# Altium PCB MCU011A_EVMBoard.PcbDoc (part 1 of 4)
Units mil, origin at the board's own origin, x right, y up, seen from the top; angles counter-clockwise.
Board outline 10115 x 9285 mil, 4 copper layers (Top Layer, GND, PWR, Bottom Layer), stack 61.2 mil thick; 438 components, 207 nets, 1196 pads, 248 vias.
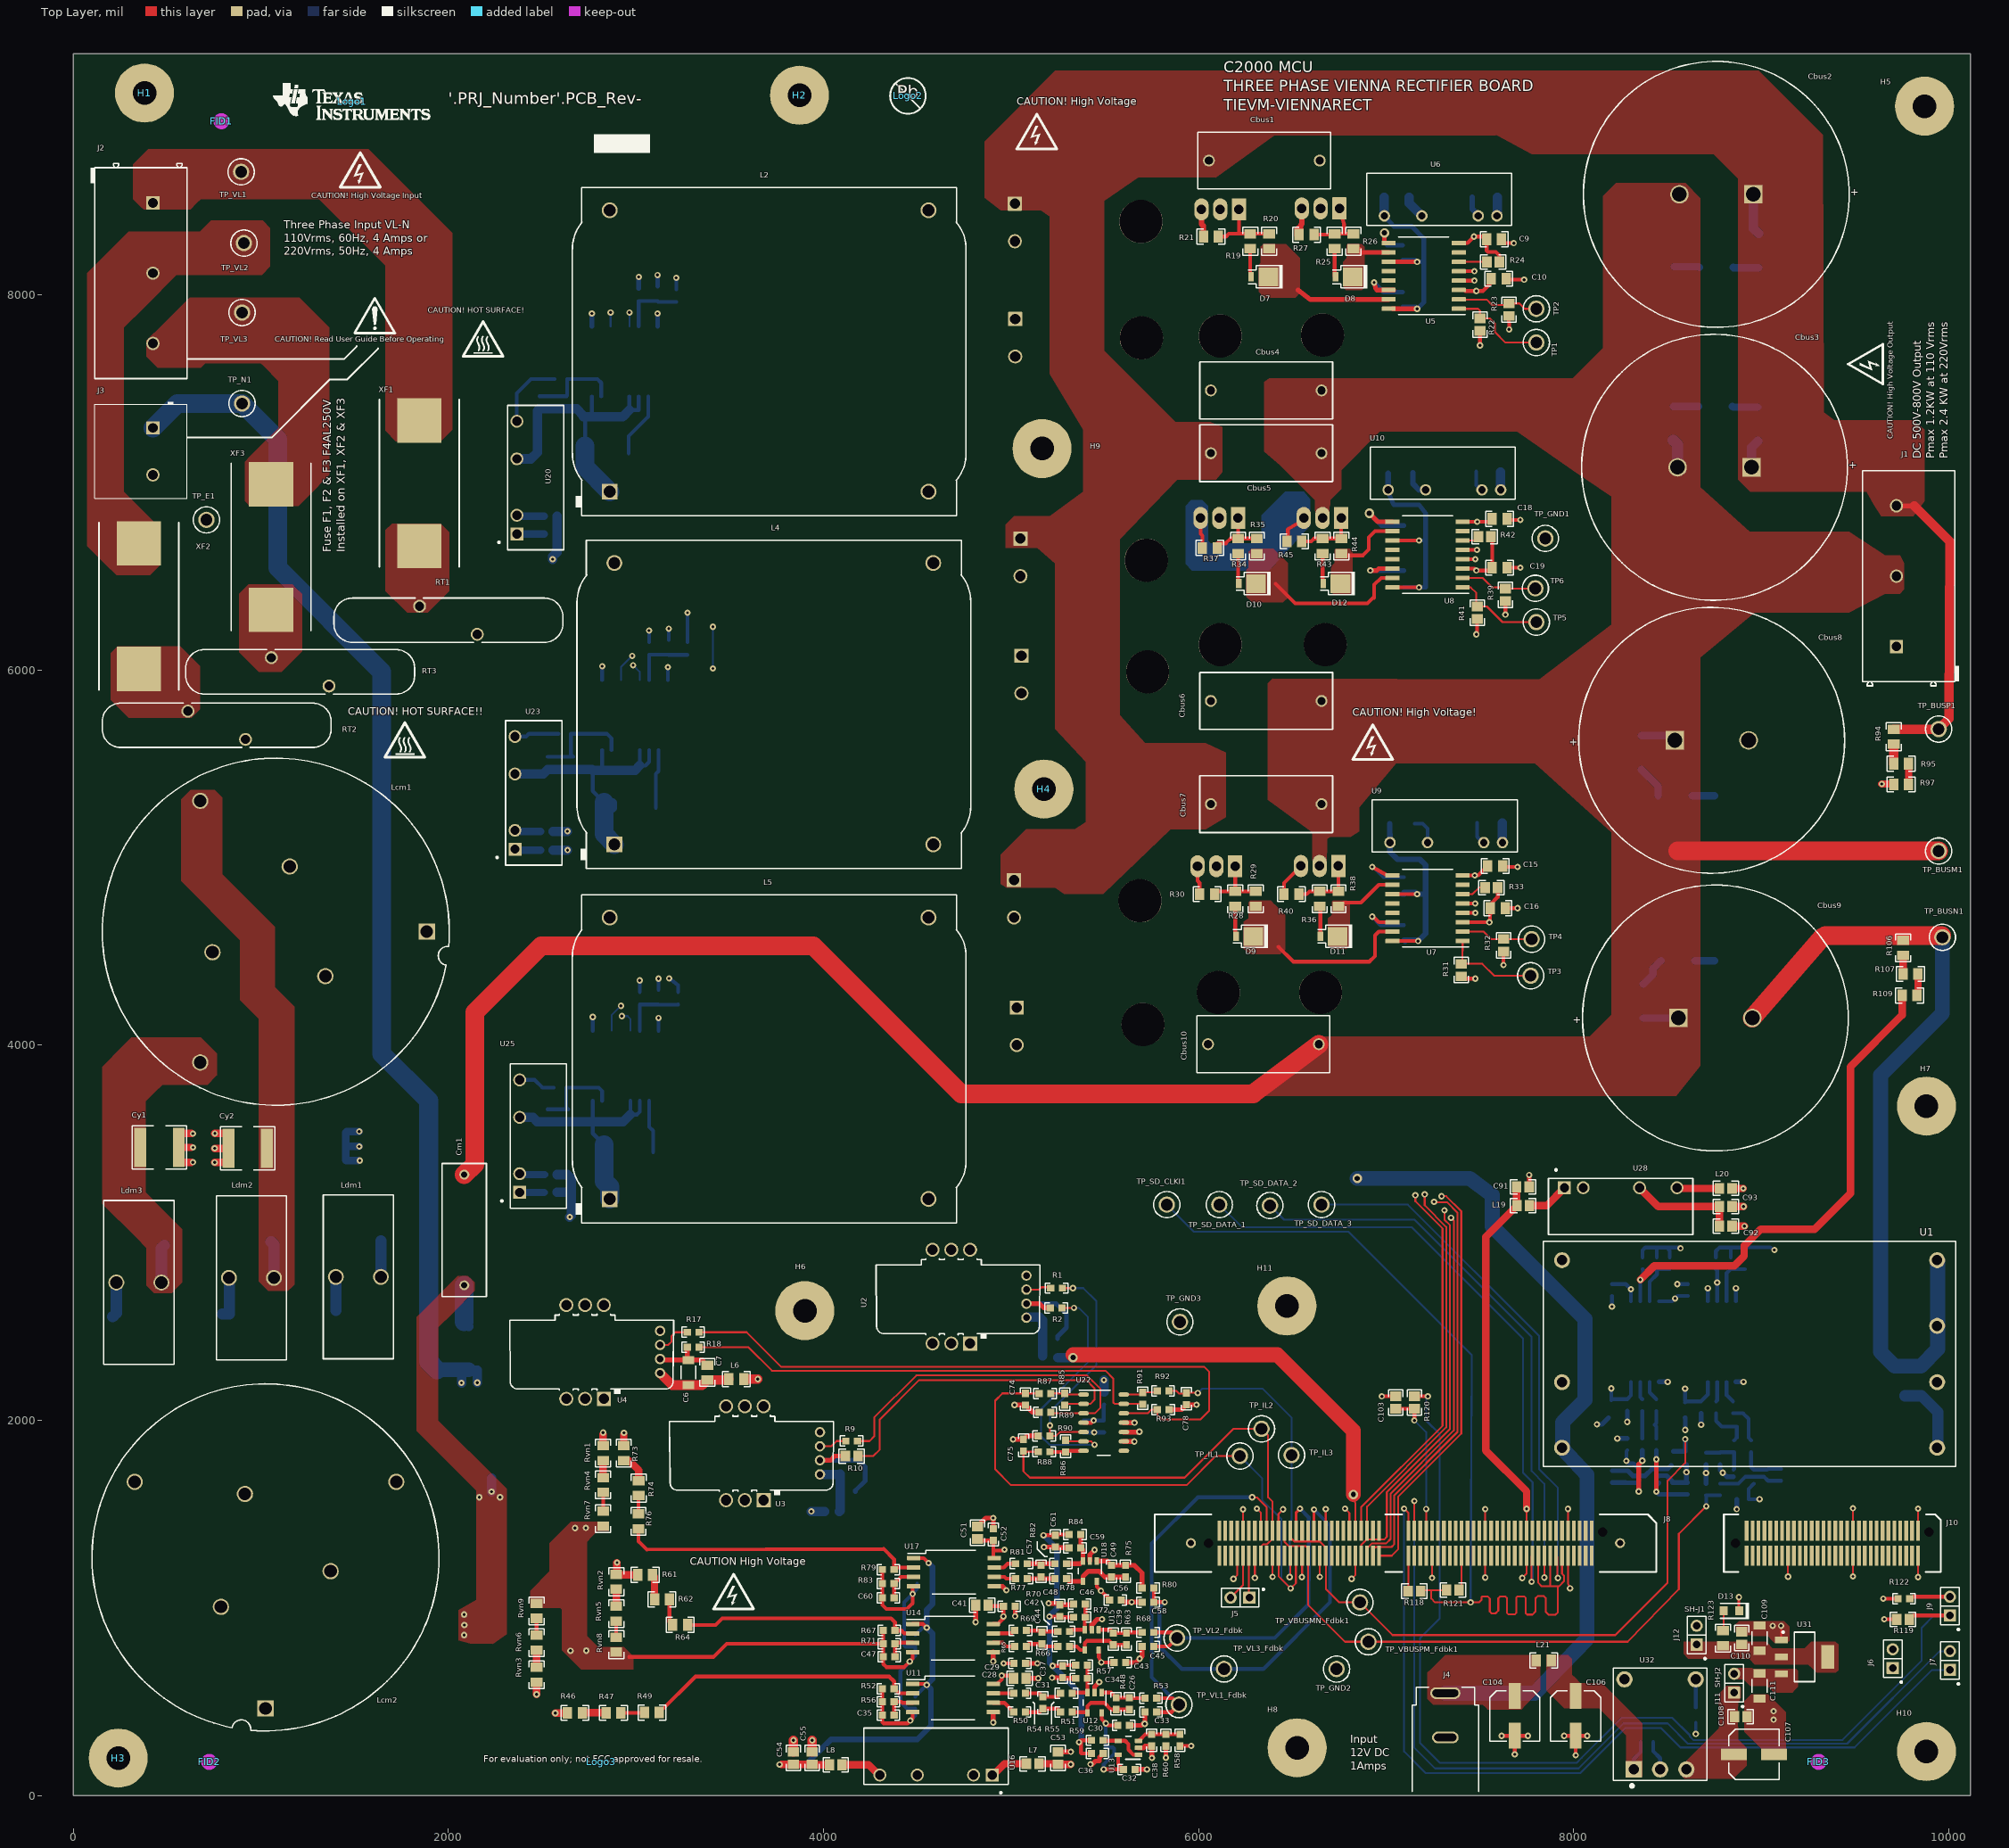
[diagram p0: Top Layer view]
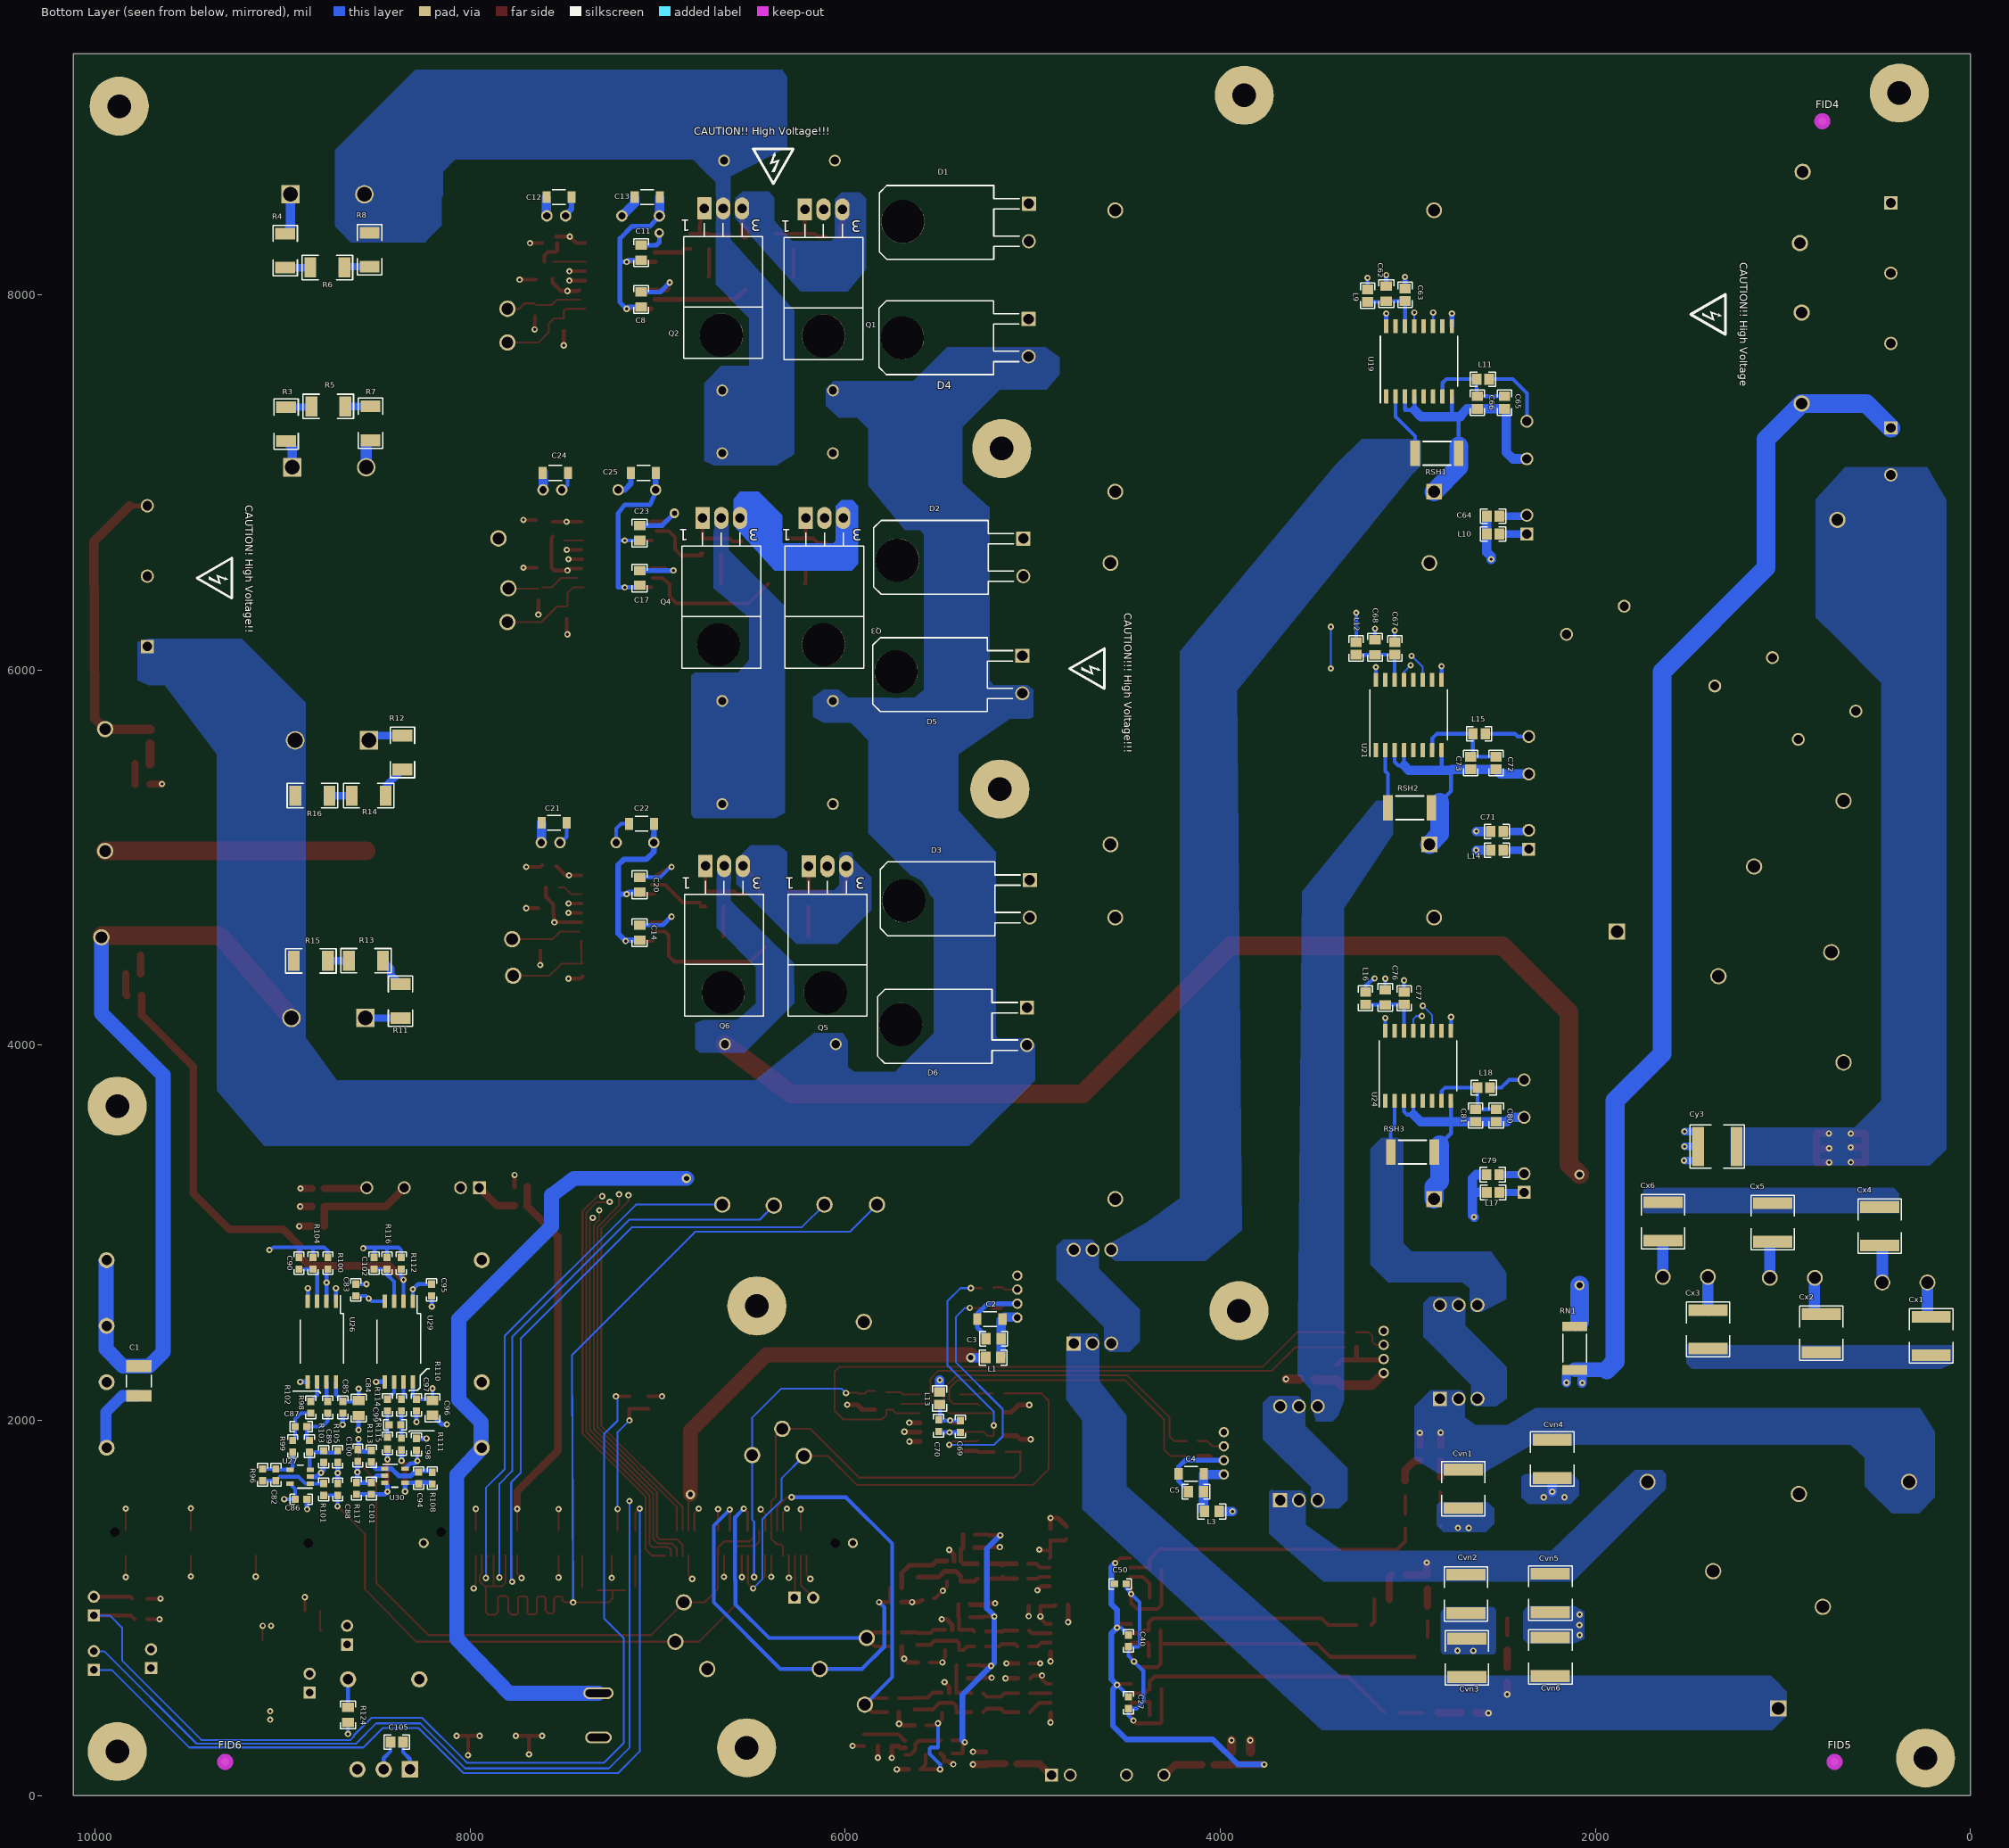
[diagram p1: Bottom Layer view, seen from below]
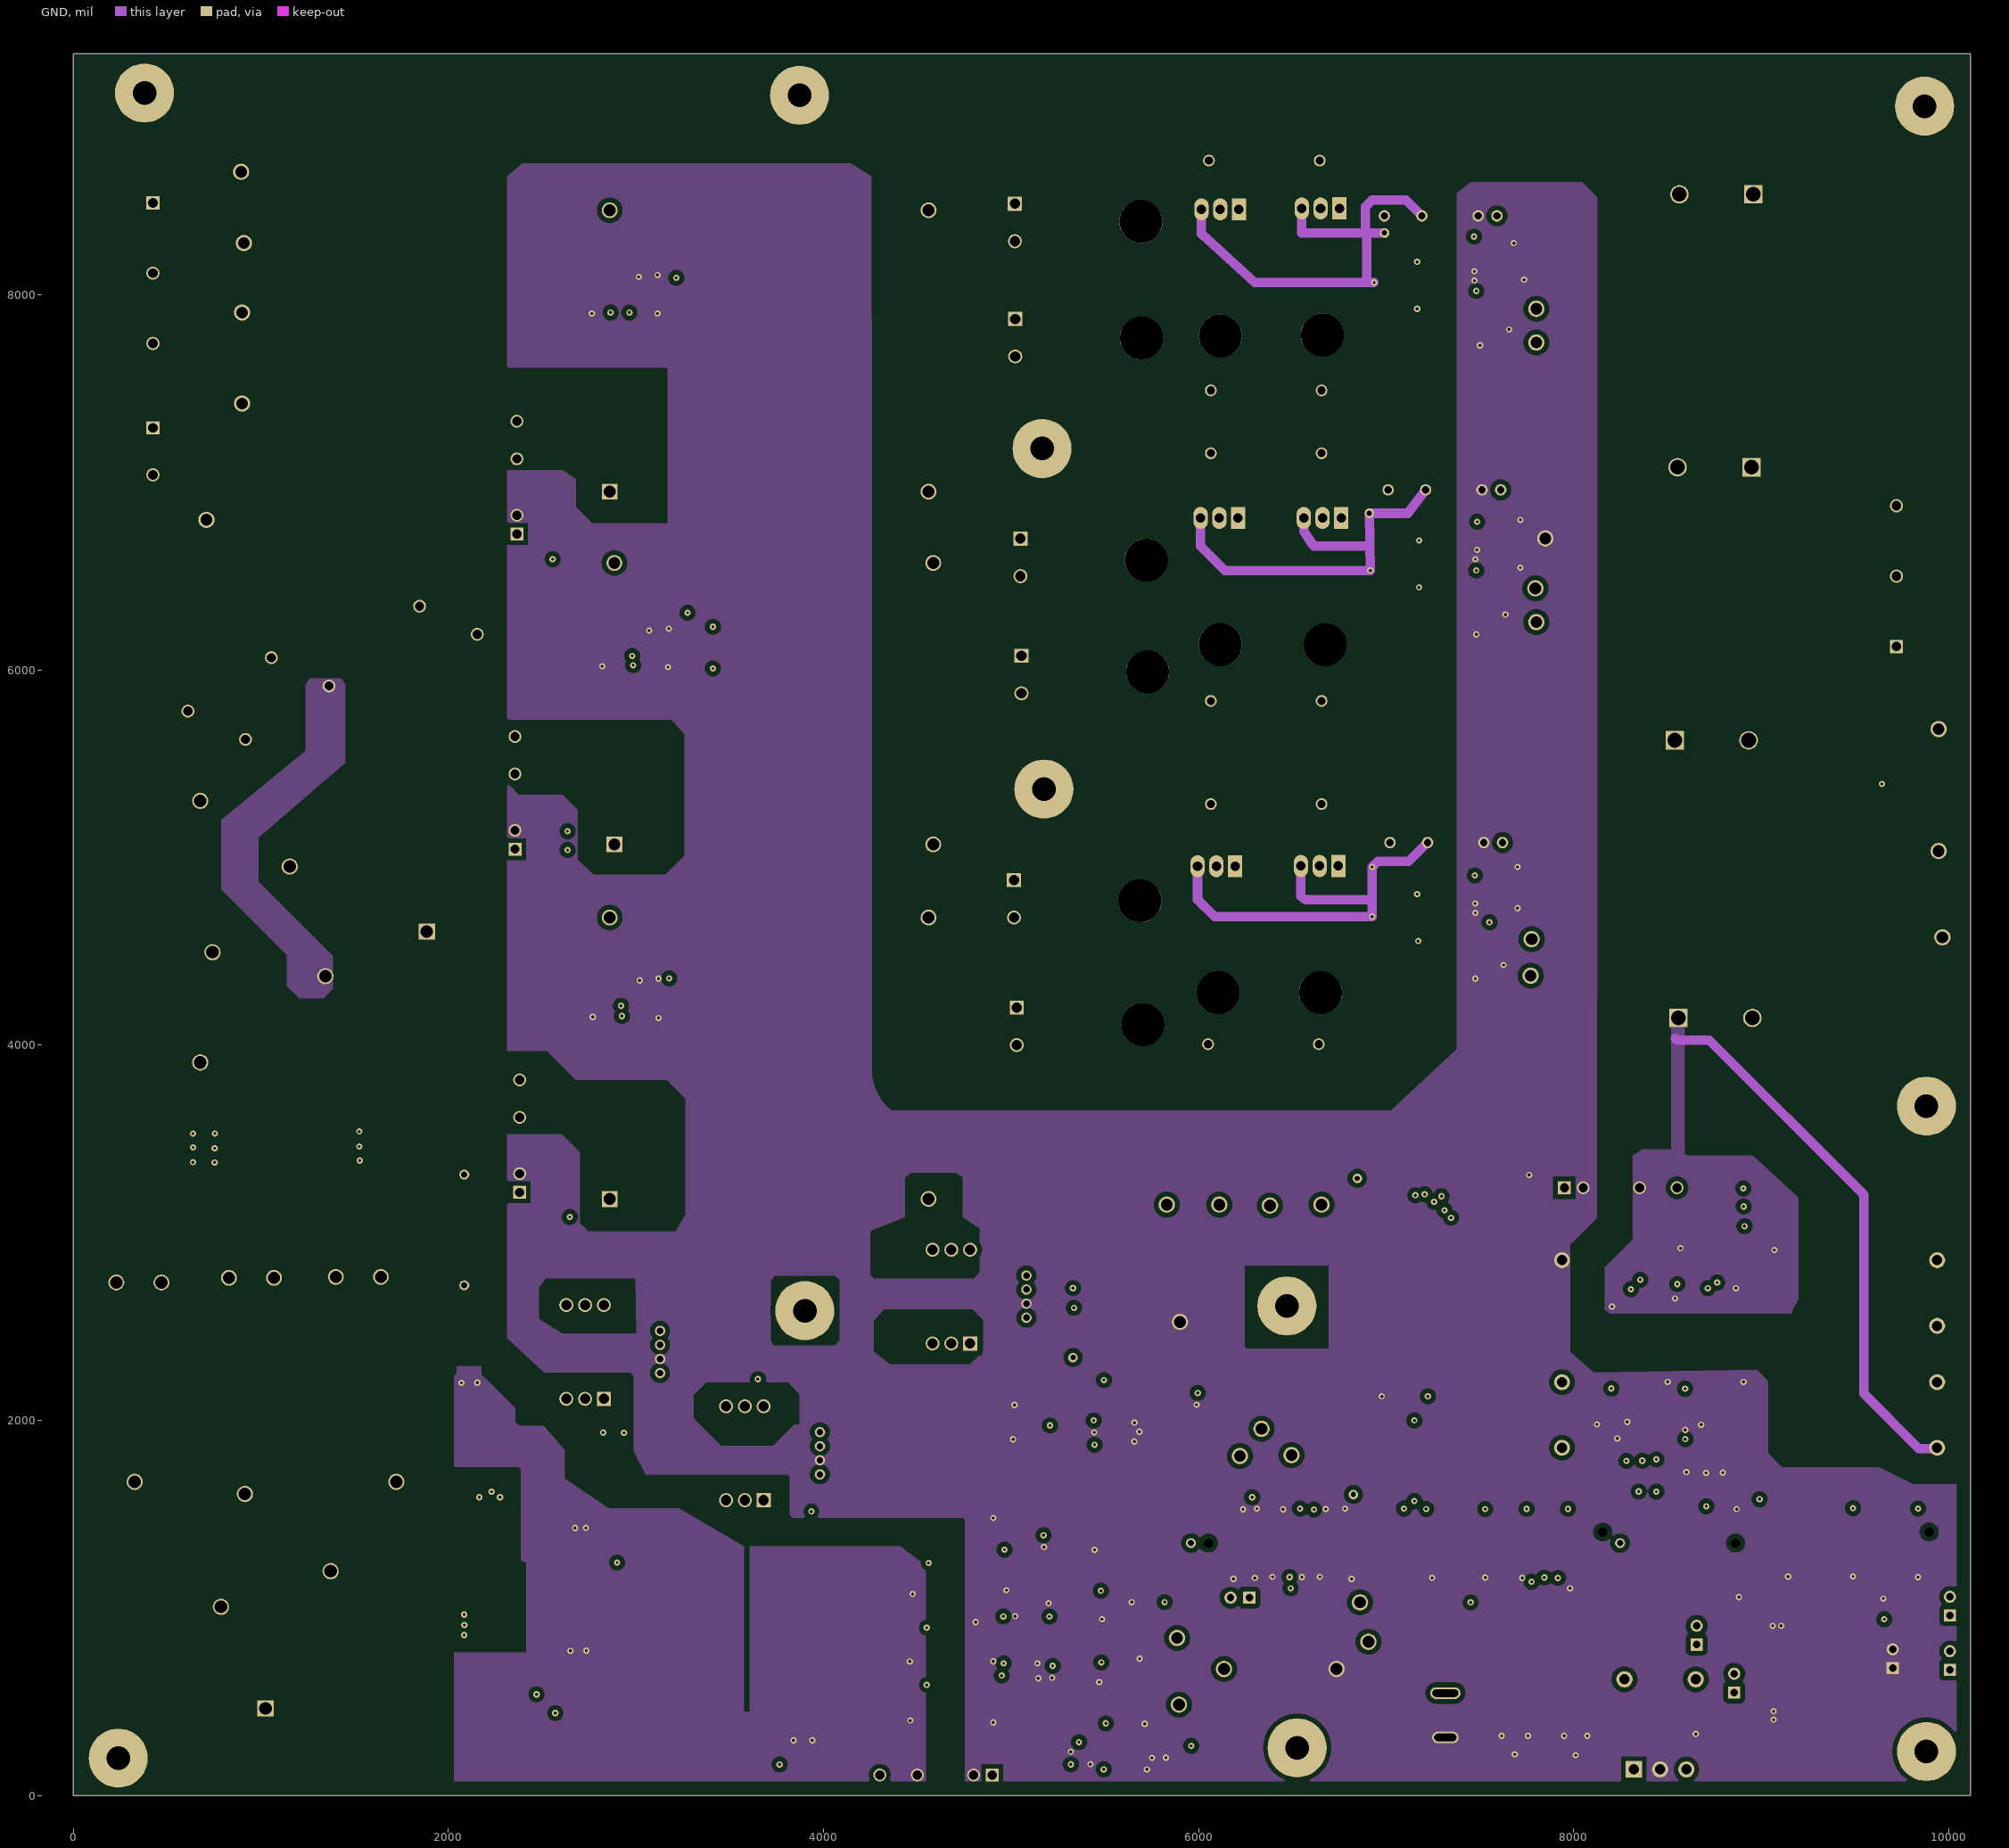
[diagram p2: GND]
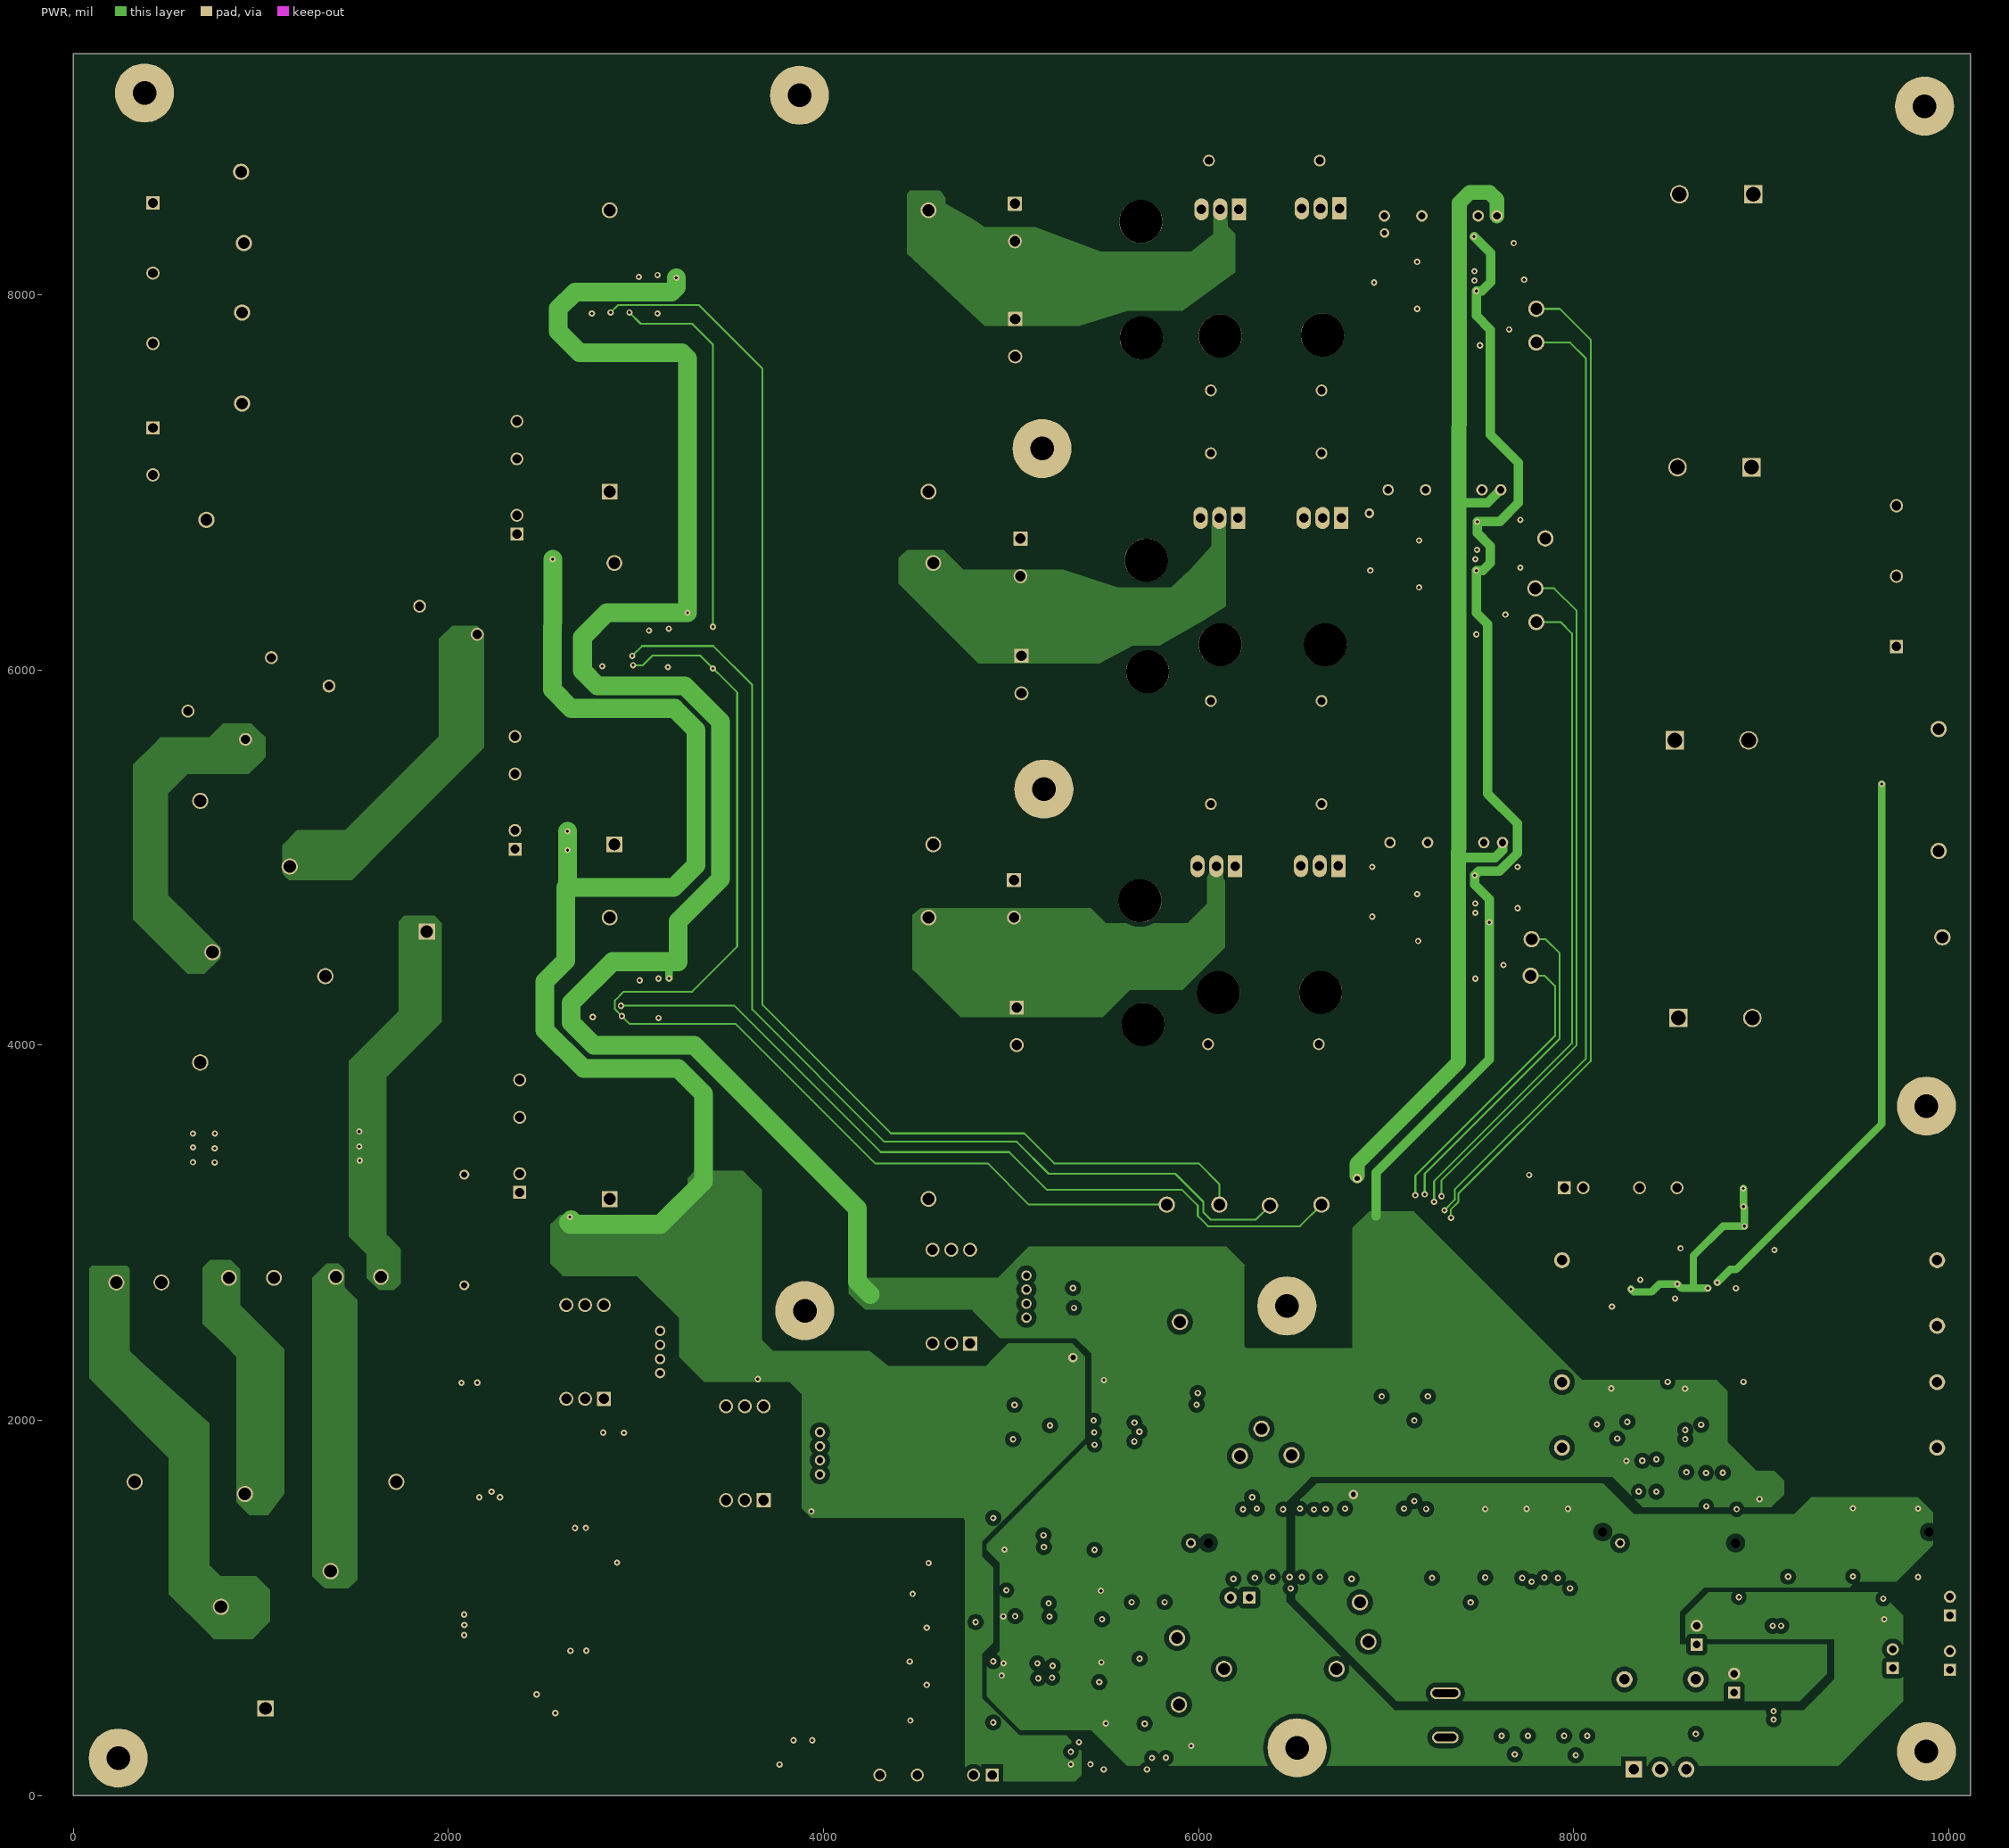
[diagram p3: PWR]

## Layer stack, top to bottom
Top Solder: solder mask 0.4, Solder Resist, Dk 3.5
Top Layer: signal copper 2.8
Dielectric1: core 15, FR-4, Dk 4.8
GND: signal copper 2.8
Dielectric 3: prepreg 20, FR-4, Dk 4.2
PWR: signal copper 2.8
Dielectric 2: core 15, FR-4, Dk 4.2
Bottom Layer: signal copper 2.8
Bottom Solder: solder mask 0.4, Solder Resist, Dk 3.5

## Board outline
0,0 10115,0 10115,9285 0,9285

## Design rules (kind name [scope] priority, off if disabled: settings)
AcuteAngle [All] p1: minimum=4.50000000000000E+0001 checktracksonly=FALSE
AssemblyTestPointUsage [All] p1: valid=2
BoardOutlineClearance BoardOutlineClearance_MountingHoles [OnCopper and InComponentClass('Mounting Holes')] p1: gap=40 ignorepadtopadclearanceinfootprint=FALSE
BoardOutlineClearance BoardOutlineClearance_Poly [OnCopper and InPoly] p2: gap=25 ignorepadtopadclearanceinfootprint=FALSE
BoardOutlineClearance [OnCopper and Not InComponentClass('Logo') and not InComponentClass('FiducialMark') and not InRegion(1000,500,4000,800)] p3: gap=75 ignorepadtopadclearanceinfootprint=FALSE
Clearance Clearance_100 [InNetClass('100')] p1: gap=100 ignorepadtopadclearanceinfootprint=FALSE except(0: Arc-Hole Track-Hole SMDPad-Hole THPad-Hole Via-Hole Fill-Hole Poly-Hole Region-Hole Text-Hole)
Clearance Clearance_Keepouts [((IsTrack Or IsArc) And Not InPoly) And IsFree and IsKeepOut vs ((IsTrack Or IsArc) And Not InPoly) And IsFree and IsKeepOut] p2: gap=0 ignorepadtopadclearanceinfootprint=FALSE
Clearance Clearance_Poly [InPolygon] p3: gap=25 ignorepadtopadclearanceinfootprint=FALSE except(0: Arc-Hole Track-Hole SMDPad-Hole THPad-Hole Via-Hole Fill-Hole Poly-Hole Region-Hole Text-Hole)
Clearance [All] p4: gap=10 ignorepadtopadclearanceinfootprint=FALSE except(0: Arc-Hole Track-Hole SMDPad-Hole THPad-Hole Via-Hole Fill-Hole Poly-Hole Region-Hole Text-Hole)
ComponentClearance ComponentClearance_MountingHoles_FiducialMarks [InComponentClass('Mounting Holes') vs InComponentClass('FiducialMark')] p1: gap=50 collisioncheckmode=3 verticalgap=10 showdistances=FALSE
ComponentClearance ComponentClearance_Shunt [InComponentClass('Header') vs InComponentClass('Shunt')] p2: gap=0 collisioncheckmode=3 verticalgap=0 showdistances=FALSE
ComponentClearance ComponentClearance_Logo [InComponentClass('Logo')] p3: gap=50 collisioncheckmode=3 verticalgap=10 showdistances=FALSE
ComponentClearance ComponentClearance_ScrewToNut [(HasFootprint('NY PMS 440 0025 PH')) vs (HasFootprint('Keystone_1902C'))] p4: gap=5 collisioncheckmode=3 verticalgap=10 showdistances=FALSE
ComponentClearance ComponentClearance_MountingHoles [InComponentClass('Mounting Holes')] p5: gap=250 collisioncheckmode=3 verticalgap=100000 showdistances=FALSE
ComponentClearance ComponentClearance_SmallPassives [HasFootprint('0201*') or HasFootprint('0402*') or HasFootprint('0508') or HasFootprint('0603*') or HasFootprint('0612') or HasFootprint('0805*') or HasFootprint('0815*') or HasFootprint('0830*') or HasFootprint('1206*') or HasFootprint('1210*') or HasFootprint('1808*') or HasFootprint('1812*') or HasFootprint('1825*') or HasFootprint('2010*') or HasFootprint('2220*') or HasFootprint('2225*') or HasFootprint('2512*') or HasFootprint('2728*') or HasFootprint('3518*') vs HasFootprint('0201*') or HasFootprint('0402*') or HasFootprint('0508') or HasFootprint('0603*') or HasFootprint('0612') or HasFootprint('0805*') or HasFootprint('0815*') or HasFootprint('0830*') or HasFootprint('1206*') or HasFootprint('1210*') or HasFootprint('1808*') or HasFootprint('1812*') or HasFootprint('1825*') or HasFootprint('2010*') or HasFootprint('2220*') or HasFootprint('2225*') or HasFootprint('2512*') or HasFootprint('2728*') or HasFootprint('3518*')] p6: gap=14.96 collisioncheckmode=3 verticalgap=10 showdistances=FALSE
ComponentClearance ComponentClearance_THtoSMT [IsThruComponent vs IsSMTComponent] p7: gap=40 collisioncheckmode=3 verticalgap=30 showdistances=FALSE
ComponentClearance ComponentClearance_THtoTH [IsThruComponent vs IsThruComponent] p8: gap=30 collisioncheckmode=3 verticalgap=30 showdistances=FALSE
ComponentClearance [All] p9: gap=30 collisioncheckmode=3 verticalgap=10 showdistances=FALSE
DiffPairsRouting [All] p1: maxlimit=100 minlimit=10 mostfreqgap=10 toplayer_minwidth=15 toplayer_maxwidth=15 toplayer_prefwidth=15 midlayer1_minwidth=15 midlayer1_maxwidth=15 midlayer1_prefwidth=15 midlayer2_minwidth=15 midlayer2_maxwidth=15 midlayer2_prefwidth=15 bottomlayer_minwidth=15 bottomlayer_maxwidth=15 bottomlayer_prefwidth=15 maxuncoupledlength=1000
FabricationTestPointUsage TestPointUsage [All] p1: valid=2 allowmultiple=FALSE
FabricationTestpoint Testpoint [All] p1: side=3 testpointundercomponent=TRUE minsize=40 maxsize=100 preferedsize=60 minholesize=0 maxholesize=40 preferedholesize=32 testpointgrid=1 allowsidetop=TRUE allowsidebottom=TRUE usegrid=TRUE gridtolerance=0.01
FanoutControl Fanout_LCC [IsLCC] p1: bgadir=Out bgaviamode=Centered fanoutstyle=Auto fanoutdirection=Alternating viagrid=1 // Fanout_LCC (Default Rule)
FanoutControl Fanout_BGA [IsBGA] p2: bgadir=Out bgaviamode=Centered fanoutstyle=Auto fanoutdirection=Alternating viagrid=1 // Fanout_BGA (Default Rule)
FanoutControl Fanout_Default [All] p4: bgadir=Out bgaviamode=Centered fanoutstyle=Auto fanoutdirection=Alternating viagrid=1 // Fanout_Default (Default Rule)
FanoutControl Fanout_Small [(CompPinCount < 5)] p5: bgadir=Out bgaviamode=Centered fanoutstyle=Auto fanoutdirection=OutThenIn viagrid=1 // Fanout_Small (Default Rule)
Height [All] p1: minheight=0 maxheight=2100 prefheight=500
HoleSize [All] p1: absolutevalues=TRUE maxlimit=251 minlimit=7.87 maxpercent=80.000 minpercent=20.000
MinimumAnnularRing MinimumAnnularRing_ThermalPadVias [IsVia and InAnyComponent] p1: minimumring=5.91
MinimumAnnularRing [All] p2: minimumring=8
MinimumSolderMaskSliver MinimumSolderMaskSliver_Logo [InComponentClass('Logo') vs InComponentClass('Logo')] p1: minsoldermaskwidth=0.7
MinimumSolderMaskSliver [All] p2: minsoldermaskwidth=3.94
PlaneConnect [All] p1: planeconnectstyle=Direct reliefexpansion=10 reliefentries=4 reliefconductorwidth=10 reliefairgap=10
PolygonConnect [All] p1: connectstyle=Direct reliefconductorwidth=10 reliefentries=4 polygonreliefangle="90 Angle" airgapwidth=10
RoutingVias ThermalPadVias [IsVia and InAnyComponent] p1: holewidth=7.87 width=19.68 viastyle="Through Hole" minholewidth=7.87 minwidth=19.68 maxholewidth=12.99 maxwidth=23.62
RoutingVias [All] p2: holewidth=16 width=34 viastyle="Through Hole" minholewidth=7.87 minwidth=26 maxholewidth=40 maxwidth=65
SilkToBoardRegionClearance [Not ((IsComment or IsDesignator) And (Hide <> 'False')) and not InRegion(1000,500,4000,800)] p1:
SilkToSilkClearance SilkToSilkClearance_Pb-FreeLogo [(HasFootprint('Pb-Free_Overlay_Medium') OR HasFootprint('Pb-Free_Overlay_Small')) vs (HasFootprint('Pb-Free_Overlay_Medium') OR HasFootprint('Pb-Free_Overlay_Small'))] p1: silktosilkclearance=0
SilkToSilkClearance [All] p2: silktosilkclearance=4
SilkToSolderMaskClearance SilkToComponentPadClearance [IsPad and InAnycomponent] p1: minsilkscreentomaskgap=3 clearancetoexposedcopper=TRUE
SilkToSolderMaskClearance "Silk to Solder Mask Opening" [All] p2: minsilkscreentomaskgap=3 clearancetoexposedcopper=FALSE
SolderMaskExpansion [All] p1: expansion=1.97
Width [All] p1: maxlimit=100 minlimit=6 preferedwidth=10 checkconnectedcopper=TRUE
14 further rules are at their usual default settings.

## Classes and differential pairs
component class U_SensingOutputVoltage: C82 C83 C84 C85 C86 C87 C88 C89 C90 C91 C92 C93 C94 C95 C96 C97 C98 C99 C100 C101 C102 L19 L20 R94 R95 R96 R97 R98 R99 R100 R101 R102 R103 R104 R105 R106 R107 R108 R109 R110 R111 R112 R113 R114 R115 R116 R117 TP_VBUSMN_Fdbk1 TP_VBUSPM_Fdbk1 U26 U27 U28 U29 U30
component class U_SensingInputVoltage: C26 C27 C28 C29 C30 C31 C32 C33 C34 C35 C36 C37 C38 C39 C40 C41 C42 C43 C44 C45 C46 C47 C48 C49 C50 C51 C52 C53 C54 C55 C56 C57 C58 C59 C60 C61 L7 L8 R46 R47 R48 R49 R50 R51 R52 R53 R54 R55 R56 R57 R58 R59 R60 R61 R62 R63 R64 R65 R66 R67 R68 R69 R70 R71 R72 R73 R74 R75 R76 R77 R78 R79 R80 R81 R82 R83 R84 TP_GND2 TP_VL1_Fdbk TP_VL2_Fdbk TP_VL3_Fdbk U11 U12 U13 U14 U15 U16 U17 U18
component class U_EMCInputFilter: Cm1 Cvn1 Cvn2 Cvn3 Cvn4 Cvn5 Cvn6 Cx1 Cx2 Cx3 Cx4 Cx5 Cx6 Cy1 Cy2 Cy3 Lcm1 Lcm2 Ldm1 Ldm2 Ldm3 RN1 RT1 RT2 RT3 Rvn1 Rvn2 Rvn3 Rvn4 Rvn5 Rvn6 Rvn7 Rvn8 Rvn9 TP_E1 TP_N1 TP_VL1 TP_VL2 TP_VL3 XF1 XF2 XF3
component class U_SensingInductorCurrent: C62 C63 C64 C65 C66 C67 C68 C69 C70 C71 C72 C73 C74 C75 C76 C77 C78 C79 C80 C81 L9 L10 L11 L12 L13 L14 L15 L16 L17 L18 R85 R86 R87 R88 R89 R90 R91 R92 R93 TP_GND3 TP_IL1 TP_IL2 TP_IL3 TP_SD_CLKI1 TP_SD_DATA_1 TP_SD_DATA_2 TP_SD_DATA_3 U19 U20 U21 U22 U23 U24 U25
component class U_PWMDrivers: C8 C9 C10 C11 C12 C13 C14 C15 C16 C17 C18 C19 C20 C21 C22 C23 C24 C25 D7 D8 D9 D10 D11 D12 R19 R20 R21 R22 R23 R24 R25 R26 R27 R28 R29 R30 R31 R32 R33 R34 R35 R36 R37 R38 R39 R40 R41 R42 R43 R44 R45 TP1 TP2 TP3 TP4 TP5 TP6 TP_GND1 U5 U6 U7 U8 U9 U10
component class U_PowerStage: C2 C3 C4 C5 C6 C7 Cbus1 Cbus2 Cbus3 Cbus4 Cbus5 Cbus6 Cbus7 Cbus8 Cbus9 Cbus10 D1 D2 D3 D4 D5 D6 L1 L2 L3 L4 L5 L6 Q1 Q2 Q3 Q4 Q5 Q6 R1 R2 R3 R4 R5 R6 R7 R8 R9 R10 R11 R12 R13 R14 R15 R16 R17 R18 RSH1 RSH2 RSH3 TP_BUSM1 TP_BUSN1 TP_BUSP1 U2 U3 U4
component class U_Controller: C103 J5 J6 J7 J8 J9 J10 R118 R119 R120 R121 R122
component class U_ControllerPower: C104 C105 C106 C107 C108 C109 C110 C111 D13 J11 J12 L21 R123 R124 U31 U32
component class Header: J5 J6 J7 J9 J11 J12
component class "Mounting Holes": H1 H2 H3 H4 H5 H6 H7 H8 H9 H10 H11
component class Logo: Logo1
component class U_EVM_Hardware: "CAUTION High Voltage" "CAUTION! High Voltage" "CAUTION! High Voltage Input" "CAUTION! High Voltage Output" "CAUTION! High Voltage!" "CAUTION! High Voltage!!" "CAUTION! HOT SURFACE!" "CAUTION! HOT SURFACE!!" "CAUTION! Read User Guide Before Operating" "CAUTION!! High Voltage" "CAUTION!! High Voltage!!!" "CAUTION!!! High Voltage!!!" FID1 FID2 FID3 FID4 FID5 FID6 H1 H2 H3 H4 H5 H6 H7 H8 H9 H10 H11 H13 Logo1 Logo2 Logo3 SH-J1 SH-J2 ZZ1 ZZ2 ZZ3 ZZ4 ZZ5 ZZ6
component class FiducialMark: FID1 FID2 FID3 FID4 FID5 FID6
component class AssemblyNote: ZZ1 ZZ2 ZZ3 ZZ4 ZZ5 ZZ6
component class Thermal: SIL1 SIL2 SIL3 SIL4 SIL5 SIL6 SIL7 SIL8 SIL9 SIL10 SIL11 SIL12
component class Shunt: SH-J1 SH-J2
component class MCU011A_CoverSheet: C1 J1 J2 J3 J4 U1

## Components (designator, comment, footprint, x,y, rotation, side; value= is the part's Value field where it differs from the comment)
C1 "1812Y5000474KXTWS2" 1812_254 9765,2210 r90 bottom value=0.47uF
C2 "C1206C106K3RACTU" 1206_190 5227.8,2540 r0 bottom value=10uF
C3 "C0805C104K3RACTU" 0805_HV 5207.8,2435 r0 bottom value=0.1uF
C4 "C1206C106K3RACTU" 1206_190 4155,1715 r0 bottom value=10uF
C5 "C0805C104K3RACTU" 0805_HV 4130,1620 r0 bottom value=0.1uF
C6 "C1206C106K3RACTU" 1206_190 3280,2255 r90 top value=10uF
C7 "C0805C104K3RACTU" 0805_HV 3380,2255 r90 top value=0.1uF
C8 "C0805C104K3RACTU" 0805_HV 7086.99,7974 r90 bottom value=0.1uF
C9 "C0805C104K3RACTU" 0805_HV 7575,8295 r0 top value=0.1uF
C10 "GRM21BR71H105KA12L" 0805_HV 7600,8085 r0 top value=1uF
C11 "C0805C104K3RACTU" 0805_HV 7086.99,8224 r90 bottom value=0.1uF
C12 "C1206C106K3RACTU" 1206_190 7525,8520 r180 bottom value=10uF
C13 "C1206C106K3RACTU" 1206_190 7055,8520 r0 bottom value=10uF
C14 "C0805C104K3RACTU" 0805_HV 7095,4600 r90 bottom value=0.1uF
C15 "C0805C104K3RACTU" 0805_HV 7580,4955 r0 top value=0.1uF
C16 "GRM21BR71H105KA12L" 0805_HV 7595,4730 r0 top value=1uF
C17 "C0805C104K3RACTU" 0805_HV 7095,6490 r90 bottom value=0.1uF
C18 "C0805C104K3RACTU" 0805_HV 7605,6805 r0 top value=0.1uF
C19 "GRM21BR71H105KA12L" 0805_HV 7605,6545 r0 top value=1uF
C20 "C0805C104K3RACTU" 0805_HV 7095,4855 r90 bottom value=0.1uF
C21 "C1206C106K3RACTU" 1206_190 7551.3,5185 r180 bottom value=10uF
C22 "C1206C106K3RACTU" 1206_190 7085,5180 r0 bottom value=10uF
C23 "C0805C104K3RACTU" 0805_HV 7095,6730 r90 bottom value=0.1uF
C24 "C1206C106K3RACTU" 1206_190 7545,7050 r180 bottom value=10uF
C25 "C1206C106K3RACTU" 1206_190 7075,7050 r0 bottom value=10uF
C26 "C0603C181J5GACTU" 0603 5630,490 r90 top value=180pF
C27 "0603YC104JAT2A" 0603 4490,495 r90 bottom value=0.1uF
C28 "C2012X5R1H475K125AB" 0805 5046.3,625 r180 top value=4.7uF
C29 "0603YC104JAT2A" 0603 5046.3,705 r180 top value=0.1uF
C30 "0603YC104JAT2A" 0603 5600,375 r0 top value=0.1uF
C31 "C0603C181J5GACTU" 0603 5170,495 r90 top value=180pF
C32 "0603YC104JAT2A" 0603 5630,140 r0 top value=0.1uF
C33 "0603YC104JAT2A" 0603 5745,445 r180 top value=0.1uF
C34 "C0603C181J5GACTU" 0603 5375,625 r180 top value=180pF
C35 "C0603C181J5GACTU" 0603 4345,430 r0 top value=180pF
C36 "0603YC104JAT2A" 0603 5460,225 r180 top value=0.1uF
C37 "0603YC104JAT2A" 0603 5275,660 r270 top value=0.1uF
C38 "0603YC104JAT2A" 0603 5750,295 r90 top value=0.1uF
C39 "C0603C181J5GACTU" 0603 5545,835 r90 top value=180pF
C40 "0603YC104JAT2A" 0603 4490,825 r270 bottom value=0.1uF
C41 "C2012X5R1H475K125AB" 0805 4845,1015 r0 top value=4.7uF
C42 "0603YC104JAT2A" 0603 4990,1010 r0 top value=0.1uF
C43 "0603YC104JAT2A" 0603 5580,710 r180 top value=0.1uF
C44 "C0603C181J5GACTU" 0603 5165,840 r90 top value=180pF
C45 "0603YC104JAT2A" 0603 5730,795 r0 top value=0.1uF
C46 "C0603C181J5GACTU" 0603 5365,1021 r180 top value=180pF
C47 "C0603C181J5GACTU" 0603 4350,740 r0 top value=180pF
C48 "0603YC104JAT2A" 0603 5260,986 r270 top value=0.1uF
C49 "C0603C181J5GACTU" 0603 5535,1196.3 r90 top value=180pF
C50 "0603YC104JAT2A" 0603 4533,1129 r0 bottom value=0.1uF
C51 "C2012X5R1H475K125AB" 0805 4820,1401.3 r270 top value=4.7uF
C52 "0603YC104JAT2A" 0603 4905,1391.3 r270 top value=0.1uF
C53 "GRM21BR71H105KA12L" 0805 5250,200 r90 top value=1uF
C54 "GRM21BR71H105KA12L" 0805 3840,200 r90 top value=1uF
C55 "C0805C104K3RACTU" 0805 3940,200 r90 top value=0.1uF
C56 "0603YC104JAT2A" 0603 5556,1042 r0 top value=0.1uF
C57 "C0603C181J5GACTU" 0603 5160,1196.3 r90 top value=180pF
C58 "0603YC104JAT2A" 0603 5730,1031.3 r180 top value=0.1uF
C59 "C0603C181J5GACTU" 0603 5340,1321.3 r180 top value=180pF
C60 "C0603C181J5GACTU" 0603 4345,1055 r0 top value=180pF
C61 "0603YC104JAT2A" 0603 5235,1356.3 r270 top value=0.1uF
C62 "0805YD225KAT2A" 0805_HV 3115,8005 r90 bottom value=2.2uF
C63 "C0805C104K3RACTU" 0805 3015,8000 r270 bottom value=0.1uF
C64 "GRM21BR71H105KA12L" 0805 2545,6820 r180 bottom value=1uF
C65 "GRM21BR71H105KA12L" 0805 2485,7425 r270 bottom value=1uF
C66 "C0805C104K3RACTU" 0805 2630,7425 r270 bottom value=0.1uF
C67 "C0805C104K3RACTU" 0805 3070,6115 r270 bottom value=0.1uF
C68 "0805YD225KAT2A" 0805_HV 3175,6120 r90 bottom value=2.2uF
C69 "0603YC104JAT2A" 0603 5385.96,1967.74 r90 bottom value=0.1uF
C70 "C0603C105K3RACTU" 0603 5501,1972 r270 bottom value=1uF
C71 "GRM21BR71H105KA12L" 0805 2525,5140 r180 bottom value=1uF
C72 "GRM21BR71H105KA12L" 0805 2530,5503.46 r270 bottom value=1uF
C73 "C0805C104K3RACTU" 0805 2665,5503.46 r270 bottom value=0.1uF
C74 "0603YC104JAT2A" 0603 5075.96,2112.74 r90 top value=0.1uF
C75 "0603YC104JAT2A" 0603 5065.96,1867.74 r270 top value=0.1uF
C76 "0805YD225KAT2A" 0805_HV 3120,4255 r90 bottom value=2.2uF
C77 "C0805C104K3RACTU" 0805 3020,4250 r270 bottom value=0.1uF
C78 "0603YC104JAT2A" 0603 5935.29,2115.26 r90 top value=0.1uF
C79 "GRM21BR71H105KA12L" 0805 2546.54,3310 r180 bottom value=1uF
C80 "GRM21BR71H105KA12L" 0805 2528.52,3625 r270 bottom value=1uF
C81 "C0805C104K3RACTU" 0805 2638.52,3625 r270 bottom value=0.1uF
C82 "C0603C181J5GACTU" 0603 9035,1710.01 r270 bottom value=180pF
C83 "0603YC104JAT2A" 0603 8608.7,2695 r270 bottom value=0.1uF
C84 "C2012X5R1H475K125AB" 0805_HV 8593,2066 r90 bottom value=4.7uF
C85 "0603YC104JAT2A" 0603 8678.09,2069.77 r270 bottom value=0.1uF
C86 "0603YC104JAT2A" 0603 8900,1580.01 r180 bottom value=0.1uF
C87 "C0603C181J5GACTU" 0603 8900,1966.95 r180 bottom value=180pF
C88 "0603YC104JAT2A" 0603 8705,1631.95 r270 bottom value=0.1uF
C89 "C0603C181J5GACTU" 0603 8780,1806.95 r270 bottom value=180pF
C90 "C0603C181J5GACTU" 0603 8911.7,2838 r270 bottom value=180pF
C91 "GRM21BR71H105KA12L" 0805 7728.46,3244.37 r0 top value=1uF
C92 "GRM21BR71H105KA12L" 0805 8810,3035 r180 top value=1uF
C93 "C0805C104K3RACTU" 0805 8810,3140 r180 top value=0.1uF
C94 "C0603C181J5GACTU" 0603 8274,1693 r90 bottom value=180pF
C95 "0603YC104JAT2A" 0603 8203.7,2695 r270 bottom value=0.1uF
C96 "C2012X5R1H475K125AB" 0805_HV 8200,2066.95 r90 bottom value=4.7uF
C97 "0603YC104JAT2A" 0603 8285,2081.95 r90 bottom value=0.1uF
C98 "0603YC104JAT2A" 0603 8285,1871.95 r90 bottom value=0.1uF
C99 "C0603C181J5GACTU" 0603 8400,1976.95 r0 bottom value=180pF
C100 "0603YC104JAT2A" 0603 8598,1813 r270 bottom value=0.1uF
C101 "C0603C181J5GACTU" 0603 8525,1636.95 r90 bottom value=180pF
C102 "C0603C181J5GACTU" 0603 8511.7,2838 r270 bottom value=180pF
C103 "C0805C104K3RACTU" 0805 7050,2095 r270 top value=0.1uF
C104 "EEH-ZA1E101XP" SM_RADIAL_6.3BMM 7685,425 r270 top value=100uF
C105 "C0805C104K3RACTU" 0805 8390,285 r180 bottom value=0.1uF
C106 "EEH-ZA1E101XP" SM_RADIAL_6.3BMM 8010,425 r270 top value=100uF
C107 "EEH-ZA1E101XP" SM_RADIAL_6.3BMM 8960,220 r0 top value=100uF
C108 "C0805C104K3RACTU" 0805 8890,420 r180 top value=0.1uF
C109 "C1206C106K3RACTU" 1206_190 8990,839.68 r90 top value=10uF
C110 "C0805C104K3RACTU" 0805 8895,839.68 r270 top value=0.1uF
C111 "C1206C106K3RACTU" 1206_190 8990,584.68 r270 top value=10uF
"CAUTION High Voltage" "DANGER HIGH VOLTAGE" IEC_HighVoltage_Small 3520,1083 r0 top
"CAUTION! High Voltage" "DANGER HIGH VOLTAGE" IEC_HighVoltage_Small 5137,8865 r0 top
"CAUTION! High Voltage Input" "DANGER HIGH VOLTAGE" IEC_HighVoltage_Small 1530,8660 r0 top
"CAUTION! High Voltage Output" "DANGER HIGH VOLTAGE" IEC_HighVoltage_Small 9560,7630 r90 top
"CAUTION! High Voltage!" "DANGER HIGH VOLTAGE" IEC_HighVoltage_Small 6928,5610 r0 top
"CAUTION! High Voltage!!" "DANGER HIGH VOLTAGE" IEC_HighVoltage_Small 9358,6490 r90 bottom
"CAUTION! HOT SURFACE!" "CAUTION HOT SURFACE" IEC_HotSurface_Small 2185,7765 r0 top
"CAUTION! HOT SURFACE!!" "CAUTION HOT SURFACE" IEC_HotSurface_Small 1768,5627 r0 top
"CAUTION! Read User Guide Before Operating" "CAUTION.  READ USER GUIDE BEFORE USE" IEC_Caution_Small 1608,7889 r0 top
"CAUTION!! High Voltage" "DANGER HIGH VOLTAGE" IEC_HighVoltage_Small 1395,7895 r90 bottom
"CAUTION!! High Voltage!!!" "DANGER HIGH VOLTAGE" IEC_HighVoltage_Small 6383,8689 r0 bottom
"CAUTION!!! High Voltage!!!" "DANGER HIGH VOLTAGE" IEC_HighVoltage_Small 4706,6007 r90 bottom
Cbus1 "ECW-F6104JL" CAPRR1500W80L1800T770H1210 6350,8715 r0 top value=0.1uF
Cbus2 "B43504C5227M" B43504_3500x3000 8760,8535 r180 top value=220uF
Cbus3 "B43504C5227M" B43504_3500x3000 8750,7080 r180 top value=220uF
Cbus4 "ECW-F6104JL" CAPRR1500W80L1800T770H1210 6360,7490 r180 top value=0.1uF
Cbus5 "ECW-F6104JL" CAPRR1500W80L1800T770H1210 6360,7155 r0 top value=0.1uF
Cbus6 "ECW-F6104JL" CAPRR1500W80L1800T770H1210 6360,5835 r180 top value=0.1uF
Cbus7 "ECW-F6104JL" CAPRR1500W80L1800T770H1210 6360,5285 r0 top value=0.1uF
Cbus8 "B43504C5227M" B43504_3500x3000 8735,5625 r0 top value=220uF
Cbus9 "B43504C5227M" B43504_3500x3000 8755,4145 r0 top value=220uF
Cbus10 "ECW-F6104JL" CAPRR1500W80L1800T770H1210 6345,4005 r180 top value=0.1uF
Cm1 "ECQ-U2A104ML" CAPRR1500W60L1750T550H1250 2085,3015 r90 top value=0.1uF
Cvn1 "GA355QR7GF222KW01L" 2220_280 2705,1635 r270 bottom value=2200pF
Cvn2 "GA355QR7GF222KW01L" 2220_280 2690,1075 r270 bottom value=2200pF
Cvn3 "GA355QR7GF222KW01L" 2220_280 2685,735 r90 bottom value=2200pF
Cvn4 "GA355QR7GF222KW01L" 2220_280 2230,1795 r270 bottom value=2200pF
Cvn5 "GA355QR7GF222KW01L" 2220_280 2240,1080 r270 bottom value=2200pF
Cvn6 "GA355QR7GF222KW01L" 2220_280 2240,740 r90 bottom value=2200pF
Cx1 "GA355QR7GF222KW01L" 2220_280 210,2450 r270 bottom value=2200pF
Cx2 "GA355QR7GF222KW01L" 2220_280 795,2465 r270 bottom value=2200pF
Cx3 "GA355QR7GF222KW01L" 2220_280 1400,2485 r270 bottom value=2200pF
Cx4 "GA355QR7GF222KW01L" 2220_280 485,3035 r90 bottom value=2200pF
Cx5 "GA355QR7GF222KW01L" 2220_280 1055,3055 r90 bottom value=2200pF
Cx6 "GA355QR7GF222KW01L" 2220_280 1640,3060 r90 bottom value=2200pF
Cy1 "GA355QR7GF222KW01L" 2220_280 460,3455 r0 top value=2200pF
Cy2 "GA355QR7GF222KW01L" 2220_280 930,3450 r180 top value=2200pF
Cy3 "GA355QR7GF222KW01L" 2220_280 1350,3460 r180 bottom value=2200pF
D1 "C4D08120A" TO-220-2_HORIZ_INV 5020,8385 r270 bottom value=1200V
D2 "C4D08120A" TO-220-2_HORIZ_INV 5050,6600 r270 bottom value=1200V
D3 "C4D08120A" TO-220-2_HORIZ_INV 5015,4780 r270 bottom value=1200V
D4 "C4D08120A" TO-220-2_HORIZ_INV 5022,7771 r270 bottom value=1200V
D5 "C4D08120A" TO-220-2_HORIZ_INV 5055,5975 r270 bottom value=1200V
D6 "C4D08120A" TO-220-2_HORIZ_INV 5030,4100 r270 bottom value=1200V
D7 "MBRM130LT1G" POWERMITE 6325,8095 r180 top value=30V
D8 "MBRM130LT1G" POWERMITE 6775,8095 r180 top value=30V
D9 "MBRM130LT1G" POWERMITE 6245,4580 r180 top value=30V
D10 "MBRM130LT1G" POWERMITE 6260,6460 r180 top value=30V
D11 "MBRM130LT1G" POWERMITE 6695,4580 r180 top value=30V
D12 "MBRM130LT1G" POWERMITE 6710,6460 r180 top value=30V
D13 "150080VS75000" WL-SMCW_Green_0805 8840,984.68 r180 top value="Bright Green"
FID1 "Fiducial" Fiducial10-20 790,8925 r0 top
FID2 "Fiducial" Fiducial10-20 725,180 r0 top
FID3 "Fiducial" Fiducial10-20 9305,180 r0 top
FID4 "Fiducial" Fiducial10-20 790,8925 r180 bottom
FID5 "Fiducial" Fiducial10-20 725,180 r180 bottom
FID6 "Fiducial" Fiducial10-20 9305,180 r180 bottom
H1 "NY PMS 440 0025 PH" "NY PMS 440 0025 PH" 380,9075 r0 top locked
H2 "NY PMS 440 0025 PH" "NY PMS 440 0025 PH" 3872,9063 r0 top locked
H3 "NY PMS 440 0025 PH" "NY PMS 440 0025 PH" 240,200 r0 top locked
H4 "NY PMS 440 0025 PH" "NY PMS 440 0025 PH" 5175,5365 r0 top locked
H5 "NY PMS 440 0025 PH" "NY PMS 440 0025 PH" 9870,9005 r90 top
H6 "NY PMS 440 0025 PH" "NY PMS 440 0025 PH" 3900,2585 r90 top
H7 "NY PMS 440 0025 PH" "NY PMS 440 0025 PH" 9880,3675 r90 top
H8 "NY PMS 440 0025 PH" "NY PMS 440 0025 PH" 6525,255 r90 top
H9 "NY PMS 440 0025 PH" "NY PMS 440 0025 PH" 5165,7180 r90 top
H10 "NY PMS 440 0025 PH" "NY PMS 440 0025 PH" 9880,235 r90 top
H11 "NY PMS 440 0025 PH" "NY PMS 440 0025 PH" 6470,2610 r90 top
J1 "1714984" Phoenix_1714984 9785,6500 r90 top
J2 "1714984" Phoenix_1714984 360,8115 r270 top
J3 "1714955" Phoenix_1714955 425,7165 r270 top
J4 "PJ-037AH" CUI_PJ-037AH 7315,428.11 r0 top
J5 "HTSW-102-07-G-S" Samtec_HTSW-102-07-G-S 6220,1055 r180 top
J6 "HTSW-102-07-G-S" Samtec_HTSW-102-07-G-S 9700,730 r90 top
J7 "HTSW-102-07-G-S" Samtec_HTSW-102-07-G-S 10005,720 r90 top
J8 "HSEC8-160-01-L-DV-A-BL" controlCARD-120HSEC 7030,1345 r0 top
J9 "HTSW-102-07-G-S" Samtec_HTSW-102-07-G-S 10005,1010 r90 top
J10 "HSEC8-130-01-L-DV-A" controlCARD-180HSEC-60pinAddon 9378.15,1345.87 r0 top locked
J11 "HTSW-102-07-G-S" Samtec_HTSW-102-07-G-S 8855,600 r90 top
J12 "HTSW-102-07-G-S" Samtec_HTSW-102-07-G-S 8655,855 r90 top
L1 "MPZ2012S300AT000" 0805_HV 5210,2335 r0 bottom value="30 ohm"
L2 "53PR116-292" 53PR116 3710,7700 r90 top
L3 "MPZ2012S300AT000" 0805_HV 4045,1515 r180 bottom value="30 ohm"
L4 "53PR116-292" 53PR116 3735,5820 r90 top
L5 "53PR116-292" 53PR116 3710,3930 r90 top
L6 "MPZ2012S300AT000" 0805_HV 3535,2220 r0 top value="30 ohm"
L7 "MPZ2012S300AT000" 0805 5115,170 r180 top value="30 ohm"
L8 "MPZ2012S300AT000" 0805 4065,165 r180 top value="30 ohm"
L9 "MPZ2012S300AT000" 0805 3215,7995 r90 bottom value="30 ohm"
L10 "MPZ2012S300AT000" 0805 2545,6725 r180 bottom value="30 ohm"
L11 "MPZ2012S300AT000" 0805 2600,7550 r0 bottom value="30 ohm"
L12 "MPZ2012S300AT000" 0805 3275,6115 r90 bottom value="30 ohm"
L13 "MPZ2012S300AT000" 0805 5495.96,2117.74 r90 bottom value="30 ohm"
L14 "MPZ2012S300AT000" 0805 2525,5040 r180 bottom value="30 ohm"
L15 "MPZ2012S300AT000" 0805 2620,5660 r0 bottom value="30 ohm"
L16 "MPZ2012S300AT000" 0805 3225,4250 r90 bottom value="30 ohm"
L17 "MPZ2012S300AT000" 0805 2545,3215 r180 bottom value="30 ohm"
L18 "MPZ2012S300AT000" 0805 2595.06,3773.46 r0 bottom value="30 ohm"
L19 "MPZ2012S300AT000" 0805 7730,3144.37 r0 top value="30 ohm"
L20 "MPZ2012S300AT000" 0805 8810,3236.48 r0 top value="30 ohm"
L21 "MPZ2012S300AT000" 0805_HV 7840,720 r180 top value="30 ohm"
Lcm1 "54PR519-165" 54PR519 1080,4605 r270 top value=1.6mH
Lcm2 "54PR519-165" 54PR519 1025,1270 r180 top value=1.6mH
Ldm1 "PA0431LNL" PA0431LNL 1520,2765 r180 top
Ldm2 "PA0431LNL" PA0431LNL 950,2760 r180 top
Ldm3 "PA0431LNL" PA0431LNL 350,2735 r180 top
Logo1 "Texas Instruments" TI_Stacked_Overlay_Small 1485,9030 r0 top
Logo2 "Pb-Free Symbol" Pb-Free_Overlay_Medium 4450,9060 r0 top
Logo3 "FCC disclaimer" FCC_disclaimer 2815,181 r0 top
Q1 "IPP65R190C7FKSA1" TO-220AB_HORIZONTAL 6115,8455 r0 bottom value=700V
Q2 "IPP65R190C7FKSA1" TO-220AB_HORIZONTAL 6650,8460 r0 bottom value=700V
Q3 "IPP65R190C7FKSA1" TO-220AB_HORIZONTAL 6110,6810 r0 bottom value=700V
Q4 "IPP65R190C7FKSA1" TO-220AB_HORIZONTAL 6660,6810 r0 bottom value=700V
Q5 "IPP65R190C7FKSA1" TO-220AB_HORIZONTAL 6094,4954 r0 bottom value=700V
Q6 "IPP65R190C7FKSA1" TO-220AB_HORIZONTAL 6645,4955 r0 bottom value=700V
R1 "ERJ-3EKF4993V" 0603 5242.8,2705 r0 top value=499k
R2 "ERJ-3EKF4993V" 0603 5240,2600 r180 top value=499k
R3 "CRCW2010510KJNEF" 2010 8980,7310.24 r270 bottom value=510k
R4 "CRCW2010510KJNEF" 2010 8985,8235 r90 bottom value=510k
R5 "CRCW2010510KJNEF" 2010 8755,7404.68 r0 bottom value=510k
R6 "CRCW2010510KJNEF" 2010 8760,8145 r0 bottom value=510k
R7 "CRCW2010510KJNEF" 2010 8530,7314.68 r90 bottom value=510k
R8 "CRCW2010510KJNEF" 2010 8535,8240 r270 bottom value=510k
R9 "ERJ-3EKF4993V" 0603 4150,1890 r0 top value=499k
R10 "CRCW0805499KFKEA" 0805 4150,1810 r180 top value=499k
R11 "CRCW2010510KJNEF" 2010 8370,4235 r270 bottom value=510k
R12 "CRCW2010510KJNEF" 2010 8360,5560 r90 bottom value=510k
R13 "CRCW2010510KJNEF" 2010 8554.45,4450 r180 bottom value=510k
R14 "CRCW2010510KJNEF" 2010 8540,5330 r180 bottom value=510k
R15 "CRCW2010510KJNEF" 2010 8848,4449 r180 bottom value=510k
R16 "CRCW2010510KJNEF" 2010 8840,5330 r180 bottom value=510k
R17 "ERJ-3EKF4993V" 0603 3305,2470 r0 top value=499k
R18 "ERJ-3EKF4993V" 0603 3305,2390 r180 top value=499k
R19 "CRCW08050000Z0EA" 0805_HV 6275,8285 r270 top value=0
R20 "CRCW080510R0JNEA" 0805_HV 6375,8285 r90 top value=10
R21 "RT0805BRD0710KL" 0805_HV 6065,8310 r0 top value=10.0k
R22 "RT0805BRD0710KL" 0805 7500,7840 r90 top value=10.0k
R23 "RT0805BRD0710KL" 0805 7655,7920 r90 top value=10.0k
R24 "CRCW08050000Z0EA" 0805 7570,8175 r0 top value=0
R25 "CRCW08050000Z0EA" 0805_HV 6725,8285 r270 top value=0
R26 "CRCW080510R0JNEA" 0805_HV 6825,8285 r90 top value=10
R27 "RT0805BRD0710KL" 0805_HV 6575,8320 r0 top value=10.0k
R28 "CRCW08050000Z0EA" 0805_HV 6195,4780 r270 top value=0
R29 "CRCW080510R0JNEA" 0805_HV 6304.24,4780 r90 top value=10
R30 "RT0805BRD0710KL" 0805_HV 6045,4805 r0 top value=10.0k
R31 "RT0805BRD0710KL" 0805 7400,4400 r90 top value=10.0k
R32 "RT0805BRD0710KL" 0805 7625,4532.4 r90 top value=10.0k
R33 "CRCW08050000Z0EA" 0805 7560,4840 r0 top value=0
R34 "CRCW08050000Z0EA" 0805_HV 6210,6660.39 r270 top value=0
R35 "CRCW080510R0JNEA" 0805_HV 6310,6660 r90 top value=10
R36 "CRCW08050000Z0EA" 0805_HV 6645,4780 r270 top value=0
R37 "RT0805BRD0710KL" 0805_HV 6060,6650 r0 top value=10.0k
R38 "CRCW080510R0JNEA" 0805_HV 6745,4780 r90 top value=10
R39 "RT0805BRD0710KL" 0805 7635,6400 r90 top value=10.0k
R40 "RT0805BRD0710KL" 0805_HV 6495,4805 r0 top value=10.0k
R41 "RT0805BRD0710KL" 0805 7485,6305 r90 top value=10.0k
R42 "CRCW08050000Z0EA" 0805 7525,6710 r0 top value=0
R43 "CRCW08050000Z0EA" 0805_HV 6660.39,6660.39 r270 top value=0
R44 "CRCW080510R0JNEA" 0805_HV 6760,6660.39 r90 top value=10
R45 "RT0805BRD0710KL" 0805_HV 6510,6685 r0 top value=10.0k
R46 "CRCW08051M00JNEA" 0805_HV 2675,441.46 r180 top value=1.0Meg
R47 "CRCW08051M00JNEA" 0805_HV 2880,441.46 r180 top value=1.0Meg
R48 "ERJ-3EKF7501V" 0603 5560,490 r90 top value=7.50k
R49 "CRCW08051M00JNEA" 0805_HV 3085,442.91 r180 top value=1.0Meg
R50 "RC0603FR-074K7L" 0603 5045,445 r0 top value=4.70k
R51 "RC0603FR-074K7L" 0603 5295,445 r0 top value=4.70k
R52 "CRCW06032K00FKEA" 0603 4345,570 r0 top value=2.00k
R53 "CRCW060368R1FKEA" 0603 5745,520 r0 top value=68.1
R54 "RC0603FR-074K7L" 0603 5045,545 r0 top value=4.70k
R55 "RC0603FR-074K7L" 0603 5295,545 r0 top value=4.70k
R56 "CRCW06032K00FKEA" 0603 4345,500 r180 top value=2.00k
R57 "ERJ-3EKF7501V" 0603 5375,695 r0 top value=7.50k
R58 "CRCW060310K0FKEA" 0603 5900,295 r270 top value=10.0k
R59 "CRCW060310R0FKEA" 0603 5460,295 r180 top value=10.0
R60 "CRCW060310K0FKEA" 0603 5825,295 r90 top value=10.0k
R61 "CRCW08051M00JNEA" 0805_HV 3049,1176.46 r180 top value=1.0Meg
R62 "CRCW08051M00JNEA" 0805_HV 3139,1046.46 r180 top value=1.0Meg
R63 "ERJ-3EKF7501V" 0603 5615,835 r90 top value=7.50k
R64 "CRCW08051M00JNEA" 0805_HV 3235,910 r180 top value=1.0Meg
R65 "RC0603FR-074K7L" 0603 5050,795 r0 top value=4.70k
R66 "RC0603FR-074K7L" 0603 5280,795 r0 top value=4.70k
R67 "CRCW06032K00FKEA" 0603 4350,880 r0 top value=2.00k
R68 "CRCW060368R1FKEA" 0603 5730,870 r0 top value=68.1
R69 "RC0603FR-074K7L" 0603 5050,880 r0 top value=4.70k
R70 "RC0603FR-074K7L" 0603 5280,875 r0 top value=4.70k
R71 "CRCW06032K00FKEA" 0603 4350,810 r180 top value=2.00k
R72 "ERJ-3EKF7501V" 0603 5365,951 r0 top value=7.50k
R73 "CRCW08051M00JNEA" 0805_HV 2935,1826 r90 top value=1.0Meg
R74 "CRCW08051M00JNEA" 0805_HV 3015,1639 r90 top value=1.0Meg
R75 "ERJ-3EKF7501V" 0603 5610,1196.3 r90 top value=7.50k
R76 "CRCW08051M00JNEA" 0805_HV 3013,1461.45 r90 top value=1.0Meg
R77 "RC0603FR-074K7L" 0603 5055,1156.3 r0 top value=4.70k
R78 "RC0603FR-074K7L" 0603 5265,1156.3 r0 top value=4.70k
R79 "CRCW06032K00FKEA" 0603 4345,1205 r0 top value=2.00k
R80 "CRCW060368R1FKEA" 0603 5730,1106.3 r0 top value=68.1
R81 "RC0603FR-074K7L" 0603 5055,1236.3 r0 top value=4.70k
R82 "RC0603FR-074K7L" 0603 5265,1236.3 r0 top value=4.70k
R83 "CRCW06032K00FKEA" 0603 4345,1130 r180 top value=2.00k
R84 "ERJ-3EKF7501V" 0603 5340,1391.3 r0 top value=7.50k
R85 "ERJ-3EKF3303V" 0603 5285.96,2112.74 r90 top value=330k
R86 "ERJ-3EKF3303V" 0603 5290.96,1862.74 r270 top value=330k
R87 "CRCW060368R1FKEA" 0603 5180.96,2142.74 r180 top value=68.1
R88 "CRCW060368R1FKEA" 0603 5175.96,1832.74 r180 top value=68.1
R89 "ERJ-3EKF3303V" 0603 5180.96,2042.74 r0 top value=330k
R90 "ERJ-3EKF3303V" 0603 5175.96,1917.74 r0 top value=330k
R91 "ERJ-3EKF3303V" 0603 5700.96,2117.74 r90 top value=330k
R92 "CRCW060368R1FKEA" 0603 5810,2157 r180 top value=68.1
R93 "ERJ-3EKF3303V" 0603 5810.96,2057.74 r180 top value=330k
R94 "CRCW08051M00JNEA" 0805_HV 9705,5644 r90 top value=1.0Meg
R95 "CRCW08051M00JNEA" 0805_HV 9745,5500 r180 top value=1.0Meg
R96 "ERJ-3EKF7501V" 0603 9105,1710.01 r270 bottom value=7.50k
R97 "CRCW08051M00JNEA" 0805_HV 9745,5390 r0 top value=1.0Meg
R98 "RC0603FR-074K7L" 0603 8848.09,2069.77 r270 bottom value=4.70k
R99 "RC0603FR-074K7L" 0603 8945,1861.95 r270 bottom value=4.70k
R100 "CRCW06032K74FKEA" 0603 8757.29,2838 r270 bottom value=2.74k
R101 "CRCW060368R1FKEA" 0603 8780,1631.95 r270 bottom value=68.1
R102 "RC0603FR-074K7L" 0603 8758.09,2069.77 r270 bottom value=4.70k
R103 "RC0603FR-074K7L" 0603 8855,1861.95 r270 bottom value=4.70k
R104 "CRCW06032K74FKEA" 0603 8836.7,2838 r90 bottom value=2.74k
R105 "ERJ-3EKF7501V" 0603 8705,1806.95 r90 bottom value=7.50k
R106 "CRCW08051M00JNEA" 0805_HV 9755,4519 r90 top value=1.0Meg
R107 "CRCW08051M00JNEA" 0805_HV 9795,4380 r180 top value=1.0Meg
R108 "ERJ-3EKF7501V" 0603 8201,1692 r90 bottom value=7.50k
R109 "RT0805BRD071ML" 0805_HV 9790,4265 r180 top value=1.00Meg
R110 "RC0603FR-074K7L" 0603 8365,2081.95 r270 bottom value=4.70k
R111 "RC0603FR-074K7L" 0603 8365,1874 r270 bottom value=4.70k
R112 "CRCW06032K74FKEA" 0603 8366.7,2838 r270 bottom value=2.74k
R113 "CRCW060368R1FKEA" 0603 8525,1809 r90 bottom value=68.1
R114 "RC0603FR-074K7L" 0603 8440,2081.95 r270 bottom value=4.70k
R115 "RC0603FR-074K7L" 0603 8440,1878 r270 bottom value=4.70k
R116 "CRCW06032K74FKEA" 0603 8441.7,2838 r90 bottom value=2.74k
R117 "ERJ-3EKF7501V" 0603 8605,1636.95 r270 bottom value=7.50k
R118 "CRCW08050000Z0EA" 0805 7149.8,1090 r0 top value=0
R119 "CRCW08053K30JNEA" 0805 9755,940 r180 top value=3.3k
R120 "RT0805BRD0710KL" 0805 7150,2095 r270 top value=10.0k
R121 "CRCW08050000Z0EA" 0805 7355,1095 r180 top value=0
R122 "CRCW060368R1FKEA" 0603 9760,1050 r0 top value=68.1
R123 "CRCW0805470RFKEA" 0805_HV 8795,839.68 r270 top value=470
R124 "CRCW0805348RFKEA" 0805_HV 8650,430 r90 bottom value=348
RN1 "CRA2512-FZ-R020ELF" 2512 2110,2385 r90 bottom value=0.02
RSH1 "CRA2512-FZ-R020ELF" 2512 2845,7155 r180 bottom value=0.02
RSH2 "CRA2512-FZ-R020ELF" 2512 2990,5265 r180 bottom value=0.02
RSH3 "CRA2512-FZ-R020ELF" 2512 2975,3430 r180 bottom value=0.02
RT1 "SL32 10015" AMETHERM_SL32 2000,6265 r0 top
RT2 "SL32 10015" AMETHERM_SL32 765,5705 r0 top
RT3 "SL32 10015" AMETHERM_SL32 1210,5990 r0 top
Rvn1 "ERJ-6ENF2004V" 0805_HV 2825,1826 r90 top value=2.00Meg
Rvn2 "ERJ-6ENF2004V" 0805_HV 2895,1140 r90 top value=2.00Meg
Rvn3 "ERJ-6ENF2004V" 0805_HV 2470,645 r270 top value=2.00Meg
Rvn4 "ERJ-6ENF2004V" 0805_HV 2825,1656 r90 top value=2.00Meg
Rvn5 "ERJ-6ENF2004V" 0805_HV 2895,970 r90 top value=2.00Meg
Rvn6 "ERJ-6ENF2004V" 0805_HV 2470,815 r270 top value=2.00Meg
Rvn7 "ERJ-6ENF2004V" 0805_HV 2825,1476 r90 top value=2.00Meg
Rvn8 "ERJ-6ENF2004V" 0805_HV 2895,805 r90 top value=2.00Meg
Rvn9 "ERJ-6ENF2004V" 0805_HV 2470,985 r270 top value=2.00Meg
SH-J1 "2SN-BK-G" 2SN-BK-G 8650,845 r90 top value=1x2
SH-J2 "2SN-BK-G" 2SN-BK-G 8845,610 r270 top value=1x2
TP1 "5014" Keystone5014 7800,7745 r0 top
TP2 "5014" Keystone5014 7800,7925 r0 top
TP3 "5014" Keystone5014 7770,4370 r0 top
TP4 "5014" Keystone5014 7775,4565 r0 top
TP5 "5014" Keystone5014 7800,6255 r0 top
TP6 "5014" Keystone5014 7795,6435 r0 top
TP_BUSM1 "5012" Keystone5012 9945,5035 r0 top
TP_BUSN1 "5011" Keystone5011 9965,4575 r180 top
TP_BUSP1 "5010" Keystone5010 9945,5685 r180 top
TP_E1 "5126" Keystone5126 710,6800 r90 top
TP_GND1 "5128" Keystone5128 7848,6701 r0 top
TP_GND2 "5128" Keystone5128 6735,675 r90 top
TP_GND3 "5128" Keystone5128 5900,2525 r180 top
TP_IL1 "5013" Keystone5013 6220,1810 r0 top
TP_IL2 "5013" Keystone5013 6335,1955 r0 top
TP_IL3 "5013" Keystone5013 6495,1815 r180 top
TP_N1 "5012" Keystone5012 900,7420 r90 top
TP_SD_CLKI1 "5129" Keystone5129 5830,3150 r90 top
TP_SD_DATA_1 "5129" Keystone5129 6110,3150 r0 top
TP_SD_DATA_2 "5129" Keystone5129 6380,3145 r0 top
TP_SD_DATA_3 "5129" Keystone5129 6655,3150 r0 top
TP_VBUSMN_Fdbk1 "5013" Keystone5013 6860,1030 r180 top
TP_VBUSPM_Fdbk1 "5013" Keystone5013 6905,820 r90 top
TP_VL1 "5011" Keystone5011 895,8655 r90 top
TP_VL1_Fdbk "5013" Keystone5013 5895,485 r90 top
TP_VL2 "5010" Keystone5010 910,8275 r90 top
TP_VL2_Fdbk "5013" Keystone5013 5885,840 r180 top
TP_VL3 "5127" Keystone5127 900,7905 r90 top value=Blue
TP_VL3_Fdbk "5013" Keystone5013 6135,675 r90 top
U1 "PWR050" PWR050 8937,2354 r180 top
U2 "LTSR 6-NP" LTSR6-NP 4752.8,2640 r180 top
U3 "LTSR 6-NP" LTSR6-NP 3652.09,1805 r180 top
U4 "LTSR 6-NP" LTSR6-NP 2799.78,2345 r180 top
U5 "UCC21520DWR" DW0016B_N 7200,8100 r180 top
U6 "RP-1212S" RP-1205S 7290,8520 r180 top
U7 "UCC21520DWR" DW0016B_N 7220,4730 r180 top
U8 "UCC21520DWR" DW0016B_N 7220,6615 r180 top
U9 "RP-1212S" RP-1205S 7320,5180 r180 top
U10 "RP-1212S" RP-1205S 7310,7060 r180 top
U11 "AMC1301DWVR" DWV0008A 4690,520 r0 top
U12 "OPA320AIDBVR" DBV0005A_N 5445,495 r270 top
U13 "OPA320AIDBVR" DBV0005A_N 5625,255 r180 top
U14 "AMC1301DWVR" DWV0008A 4690,840 r0 top
U15 "OPA320AIDBVR" DBV0005A_N 5430,830 r270 top
U16 "DCH010505SN7" EDJ0004A 4600,110 r180 top
U17 "AMC1301DWVR" DWV0008A 4695,1191.3 r0 top
U18 "OPA320AIDBVR" DBV0005A_N 5420,1196.3 r270 top
U19 "AMC1305M25DWR" DW0016B_N 2940,7645 r90 bottom
U20 "DCH010505SN7" EDJ0004A 2365,7025 r90 top
U21 "AMC1305M25DWR" DW0016B_N 2995,5759.69 r90 bottom
U22 "OPA4350UA" D0014A_N 5493.68,1987.74 r0 top
U23 "DCH010505SN7" EDJ0004A 2355,5345 r90 top
U24 "AMC1305M25DWR" DW0016B_N 2945,3890 r90 bottom
U25 "DCH010505SN7" EDJ0004A 2380,3515 r90 top
U26 "AMC1301DWVR" DWV0008A 8789.41,2420 r270 bottom
U27 "OPA320AIDBVR" DBV0005A_N 8905,1700 r0 bottom
U28 "DCH010505SN7" EDJ0004A 8250,3240 r0 top
U29 "AMC1301DWVR" DWV0008A 8379.41,2420 r270 bottom
U30 "OPA320AIDBVR" DBV0005A_N 8400,1705.01 r180 bottom
U31 "TLV1117-33IDCY" DCY0004A_N 9230,739.68 r0 top
U32 "PTH08080WAH" EUF0005A 8460,380 r90 top
XF1 "65800001009" FuseHolder_65800001009 1845,6995 r90 top
XF2 "65800001009" FuseHolder_65800001009 350,6340 r90 top
XF3 "65800001009" FuseHolder_65800001009 1055,6655 r90 top
ZZ1 "These assemblies are ESD sensitive, ESD precautions shall be observed." AssemblyNote 242,10723.11 r0 top
ZZ2 "These assemblies must be clean and free from flux and all contaminants. Use of no clean flux is not acceptable." AssemblyNote 242,10634.56 r0 top
ZZ3 "These assemblies must comply with workmanship standards IPC-A-610 Class 2, unless otherwise specified." AssemblyNote 242,10546 r0 top
ZZ4 "Mount heatsink H16 as specified in the mechanical drawing and assembly instructions provided separately" AssemblyNote 243,10417 r0 top
ZZ5 "Paste SIL1-16 on the heat sink or on the back of D1-D6, Q1-Q6, place the insulators H17-H28 on D1-D6 and Q1-Q6" AssemblyNote 242,10282 r0 top
ZZ6 "Place Fuses F1-F3 in fuse holder XF1-XF3" AssemblyNote 243,10157 r0 top

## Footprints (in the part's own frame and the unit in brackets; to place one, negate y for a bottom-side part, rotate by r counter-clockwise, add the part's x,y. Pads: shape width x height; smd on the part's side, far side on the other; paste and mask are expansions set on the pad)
2SN-BK-G [mil] "Samtec STEP model"
  round 1 on Mech3: 0(0,0)
  body extent -78,-39 79,39, height 188
53PR116 [mm] "TH, 4-Leads, Body 50.8x44.45mm"
  rect 2.15x2.15 hole 1.61: 1(-19.05,21.59)
  round 2.15 hole 1.61: 2(-19.05,-21.59) 3(19.05,-21.59) 4(19.05,21.59)
  silkscreen extent -22.31,-26.67 22.14,26.67, body extent -22.22,-26.67 22.23,26.67, height 53.34
54PR519 [mm] "TH, 6-Leads, Dia 1850mil"
  rect 2.2x2.2 hole 1.7: 1(0,20.447)
  round 2.2 hole 1.7: 2(-8.82,1.875) 3(-17.708,-10.224) 4(2.786,-8.576) 5(17.708,-10.223) 6(6.034,6.701)
  silkscreen extent -23.49,-23.49 23.49,23.49, body extent -23.49,-23.49 23.49,23.49, height 21.58
0603 [mm] "0603 from SM-752 data"
  rect 1x0.95 smd: 1(-0.8,0) 2(0.8,0)
  silkscreen extent -1.52,-0.69 1.52,0.69, body extent -0.87,-0.47 0.87,0.47, height 1
0805 [mm] "0805 from SM-752 data"
  rect 1.3x1.5 smd: 1(-0.85,0) 2(0.85,0)
  silkscreen extent -1.72,-0.97 1.72,0.97, body extent -1.1,-0.72 1.1,0.72, height 1.45
0805_HV [mil] "0805 with 30mil clearance between pads"
  rect 50x63 smd: 1(-40,0) 2(40,0)
  silkscreen extent -74,-40 74,40, body extent -43,-29 43,29, height 57
1206_190 [mm] "1206_190"
  rect 1.1x1.6 smd: 1(-1.7,0) 2(1.7,0)
  silkscreen extent -0.9,-1 0.9,1, body extent -1.75,-0.95 1.75,0.95, height 1.9
1812_254 [mm] "SMD, 2-Leads, Body 4.8x3.4mm"
  rect 1.6x3.4 smd: 1(-2,0) 2(2,0)
  silkscreen extent -0.8,-1.7 0.8,1.7, body extent -2.4,-1.7 2.4,1.7, height 2.54
2010 [mm] "Chip Capacitor, Body 5.08x2.54mm, IPC Medium Density"
  rect 1.6x2.7 smd: 1(-2.3,0) 2(2.3,0)
  silkscreen extent -3.42,-1.65 3.42,1.65, body extent -2.73,-1.45 2.73,1.45, height 1.66
2220_280 [mm] "Chip Capacitor, Body 5.7x5.0mm, IPC Medium Density"
  rect 1.6x5.3 smd: 1(-2.6,0) 2(2.6,0)
  silkscreen extent -3.69,-2.94 3.69,2.94, body extent -2.95,-2.62 2.95,2.62, height 2.8
2512 [mm] "Chip Resistor, Body 6.3x3.2mm, IPC Medium Density"
  rect 1.3x3.4 smd: 1(-2.95,0) 2(2.95,0)
  silkscreen extent -1.9,-1.6 1.9,1.6, body extent -3.22,-1.67 3.22,1.67, height 0.71
AMETHERM_SL32 [mm] "TH, 2-Leads, Dia 31mm"
  round 1.75 hole 1.25: 1(-3.9,1.91) 2(3.9,-1.91)
  silkscreen extent -15.5,-3 15.5,3, body extent -15.5,-3 15.5,3, height 38.79
AssemblyNote [mil] "Assembly Note"
B43504_3500x3000 [mm] "TH, 2-Leads, Dia 35mm, Lead Spacing 10mm"
  rect 2.5x2.5 hole 2: 1(-5,0)
  round 2.5 hole 2: 2(5,0)
  silkscreen extent -18,-18 18,18, body extent -17.86,-17.97 17.94,17.97, height 32.01
CAPRR1500W60L1750T550H1250 [mm] "PANASONIC"
  round 1.35 hole 0.85: 1(-7.5,0) 2(7.5,0)
  silkscreen extent -9,-3 9,3, body extent -9.05,-3.05 9.05,3.05, height 13
CAPRR1500W80L1800T770H1210 [mm] "PANASONIC"
  round 1.6 hole 1.1: 1(-7.5,0) 2(7.5,0)
  silkscreen extent -9,-3.85 9,3.85, body extent -9,-3.85 9,3.85, height 13.6
controlCARD-120HSEC [mm] "Pads are not numbered according to Samtec datasheet."
  rect 0.5x2.724 smd: 1(-23.357,-1.678) 2(-23.357,1.722) 3(-22.557,-1.678) 4(-22.557,1.722) 5(-21.757,-1.678) 6(-21.757,1.722) 7(-20.957,-1.678) 8(-20.957,1.722) 9(-20.157,-1.678) 10(-20.157,1.722) 11(-19.357,-1.678) 12(-19.357,1.722) 13(-18.557,-1.678) 14(-18.557,1.722) 15(-17.757,-1.678) 16(-17.757,1.722) 17(-16.957,-1.678) 18(-16.957,1.722) 19(-16.157,-1.678) 20(-16.157,1.722) 21(-15.357,-1.678) 22(-15.357,1.722) 23(-14.557,-1.678) 24(-14.557,1.722) 25(-13.757,-1.678) 26(-13.757,1.722) 27(-12.957,-1.678) 28(-12.957,1.722) 29(-12.157,-1.678) 30(-12.157,1.722) 31(-11.357,-1.678) 32(-11.357,1.722) 33(-10.557,-1.678) 34(-10.557,1.722) 35(-9.757,-1.678) 36(-9.757,1.722) 37(-8.957,-1.678) 38(-8.957,1.722) 39(-8.157,-1.678) 40(-8.157,1.722) 41(-7.357,-1.678) 42(-7.357,1.722) 43(-6.557,-1.678) 44(-6.557,1.722) 45(-5.757,-1.678) 46(-5.757,1.722) 47(-4.957,-1.678) 48(-4.957,1.722) 49(-4.157,-1.678) 50(-4.157,1.722) 51(-3.357,-1.678) 52(-3.357,1.722) 53(-2.557,-1.678) 54(-2.557,1.722) 55(-1.757,-1.678) 56(-1.757,1.722) 57(2.243,-1.678) 58(2.243,1.722) 59(3.043,-1.678) 60(3.043,1.722) 61(3.843,-1.678) 62(3.843,1.722) 63(4.643,-1.678) 64(4.643,1.722) 65(5.443,-1.678) 66(5.443,1.722) 67(6.243,-1.678) 68(6.243,1.722) 69(7.043,-1.678) 70(7.043,1.722) 71(7.843,-1.678) 72(7.843,1.722) 73(8.643,-1.678) 74(8.643,1.722) 75(9.443,-1.678) 76(9.443,1.722) 77(10.243,-1.678) 78(10.243,1.722) 79(11.043,-1.678) 80(11.043,1.722) 81(11.843,-1.678) 82(11.843,1.722) 83(12.643,-1.678) 84(12.643,1.722) 85(13.443,-1.678) 86(13.443,1.722) 87(14.243,-1.678) 88(14.243,1.722) 89(15.043,-1.678) 90(15.043,1.722) 91(15.843,-1.678) 92(15.843,1.722) 93(16.643,-1.678) 94(16.643,1.722) 95(17.443,-1.678) 96(17.443,1.722) 97(18.243,-1.678) 98(18.243,1.722) 99(19.043,-1.678) 100(19.043,1.722) 101(19.843,-1.678) 102(19.843,1.722) 103(20.643,-1.678) 104(20.643,1.722) 105(21.443,-1.678) 106(21.443,1.722) 107(22.243,-1.678) 108(22.243,1.722) 109(23.043,-1.678) 110(23.043,1.722) 111(23.843,-1.678) 112(23.843,1.722) 113(24.643,-1.678) 114(24.643,1.722) 115(25.443,-1.678) 116(25.443,1.722) 117(26.243,-1.678) 118(26.243,1.722) 119(27.043,-1.678) 120(27.043,1.722)
  round 0.025 hole 1.27 unplated mask+0.876: 181(-24.857,0.022) 182(28.543,1.522)
  round 1.348 hole 0.84: 185(-27.207,0.022) 186(30.893,0.022)
  silkscreen extent -32.11,-3.86 35.8,3.9, body extent -31.75,-3.48 35.3,3.52, height 12.35
controlCARD-180HSEC-60pinAddon [mm] "Pads are not numbered according to datasheet."
  round 0.025 hole 1.27 unplated mask+0.876: 61(-13.1,0) 62(13.1,1.5)
  rect 0.5x2.724 smd: 121(-11.6,-1.7) 122(-11.6,1.7) 123(-10.8,-1.7) 124(-10.8,1.7) 125(-10,-1.7) 126(-10,1.7) 127(-9.2,-1.7) 128(-9.2,1.7) 129(-8.4,-1.7) 130(-8.4,1.7) 131(-7.6,-1.7) 132(-7.6,1.7) 133(-6.8,-1.7) 134(-6.8,1.7) 135(-6,-1.7) 136(-6,1.7) 137(-5.2,-1.7) 138(-5.2,1.7) 139(-4.4,-1.7) 140(-4.4,1.7) 141(-3.6,-1.7) 142(-3.6,1.7) 143(-2.8,-1.7) 144(-2.8,1.7) 145(-2,-1.7) 146(-2,1.7) 147(-1.2,-1.7) 148(-1.2,1.7) 149(-0.4,-1.7) 150(-0.4,1.7) 151(0.4,-1.7) 152(0.4,1.7) 153(1.2,-1.7) 154(1.2,1.7) 155(2,-1.7) 156(2,1.7) 157(2.8,-1.7) 158(2.8,1.7) 159(3.6,-1.7) 160(3.6,1.7) 161(4.4,-1.7) 162(4.4,1.7) 163(5.2,-1.7) 164(5.2,1.7) 165(6,-1.7) 166(6,1.7) 167(6.8,-1.7) 168(6.8,1.7) 169(7.6,-1.7) 170(7.6,1.7) 171(8.4,-1.7) 172(8.4,1.7) 173(9.2,-1.7) 174(9.2,1.7) 175(10,-1.7) 176(10,1.7) 177(10.8,-1.7) 178(10.8,1.7) 179(11.6,-1.7) 180(11.6,1.7)
  silkscreen extent -14.68,-3.88 14.68,3.88, body extent -14.3,-3.5 14.3,3.5, height 7.95
CUI_PJ-037AH [mm] "Power Jack, 2mm, R/A, TH"
  oval 4.1x1.6 hole 1 slot 3.5 at 0 deg: 1(0,3)
  oval 3.6x1.6 hole 1 slot 3 at 0 deg: 2(0,-3)
  silkscreen extent -4.5,-10.3 4.5,3.8, body extent -4.5,-10.7 4.5,3.8, height 11
D0014A_N [mm] "SOIC, 14-Leads, Body 8.7x3.9mm, Pitch 1.27mm, IPC Medium Density"
  oval 1.45x0.6 smd: 1(-2.725,3.81) 2(-2.725,2.54) 3(-2.725,1.27) 4(-2.725,0) 5(-2.725,-1.27) 6(-2.725,-2.54) 7(-2.725,-3.81) 8(2.725,-3.81) 9(2.725,-2.54) 10(2.725,-1.27) 11(2.725,0) 12(2.725,1.27) 13(2.725,2.54) 14(2.725,3.81)
  silkscreen extent -3.3,-4.4 0.9,4.4, body extent -3.02,-4.32 3.02,4.32, height 1.6
DBV0005A_N [mm] "SOT23, 5-Leads, Body 2.9x1.6mm, Pitch 0.95mm, Lead Span 2.8mm, IPC Medium Density"
  rrect17% 1x0.6 smd: 1(-1.375,0.95) 2(-1.375,0) 3(-1.375,-0.95) 4(1.375,-0.95) 5(1.375,0.95)
  silkscreen extent -1.63,-1.55 0.38,1.55, body extent -1.42,-1.46 1.42,1.46, height 1.09
DCY0004A_N [mm] "SOT223/SC73, 4-Leads, Body 6.5x3.5mm, Pitch 2.3mm, Lead Span 7mm, IPC Medium Density"
  rrect11% 1.75x0.9 smd: 1(-3.125,2.3) 2(-3.125,0) 3(-3.125,-2.3)
  rrect6% 1.75x3.2 smd: 4(3.125,0)
  silkscreen extent -3.02,-3.35 1.4,3.47, body extent -3.48,-3.25 3.48,3.25, height 1.68
DW0016B_N [mm] "SOIC, 16-Leads, Body 10.5x7.6mm, Pitch 1.27mm, IPC Medium Density"
  rrect17% 1.9x0.6 smd: 1(-4.75,4.445) 2(-4.75,3.175) 3(-4.75,1.905) 4(-4.75,0.635) 5(-4.75,-0.635) 6(-4.75,-1.905) 7(-4.75,-3.175) 8(-4.75,-4.445) 9(4.75,-4.445) 10(4.75,-3.175) 11(4.75,-1.905) 12(4.75,-0.635) 13(4.75,0.635) 14(4.75,1.905) 15(4.75,3.175) 16(4.75,4.445)
  silkscreen extent -5.6,-5.25 3.4,5.25, body extent -5.17,-5.15 5.17,5.15, height 2.59
DWV0008A [mm] "SOIC, 8-Leads, Body 5.95x7.6mm (max), Pitch 1.27mm"
  rrect17% 1.8x0.6 smd: 1(-5.45,1.905) 2(-5.45,0.635) 3(-5.45,-0.635) 4(-5.45,-1.905) 5(5.45,-1.905) 6(5.45,-0.635) 7(5.45,0.635) 8(5.45,1.905)
  silkscreen extent -6.25,-2.95 2.98,2.95, body extent -5.77,-2.92 5.77,2.93, height 2.67
EDJ0004A [mm] "Module, 4-Leads, Body 19.56x7.62mm"
  rect 1.75x1.75 hole 1.25: 1(-7.62,0)
  round 1.75 hole 1.25: 2(-5.08,0) 5(2.54,0) 7(7.62,0)
  silkscreen extent -9.78,-6.35 9.78,2.54, body extent -9.78,-6.35 9.78,1.27, height 10.15
EUF0005A [mm]
  rect 2.2x2.2 hole 1.4: 1(-6.096,3.556)
  round 2.2 hole 1.4: 2(-6.096,0) 3(-6.096,-3.556) 4(6.096,-4.826) 5(6.096,4.826)
  silkscreen extent -8.53,-6.35 7.62,6.35, body extent -7.62,-6.35 7.62,6.35, height 8.18
FCC_disclaimer [mil]
Fiducial10-20 [mm]
  round 1 smd mask+0.5: 1(0,0)
  Top Layer keep-out circle w1.178: c0,0 r0.5
FuseHolder_65800001009 [mm] "SMD, 2-Leads, Body 22.7x10.8mm, Pitch 17mm"
  rect 6x6 smd: 1(-8.5,0) 2(8.5,0)
  silkscreen extent -11.35,-5.4 11.35,5.4, body extent -11.35,-5.4 11.35,5.4, height 13.2
IEC_Caution_Small [mil]
  silkscreen extent -107,-93 107,92
IEC_HighVoltage_Small [mil]
  silkscreen extent -107,-88 107,97
IEC_HotSurface_Small [mil]
  silkscreen extent -107,-93 107,92
Keystone5010 [mil] "Keystone Multipurpose loops"
  round 87 hole 63: 1(0,0)
  silkscreen extent -70,-70 70,70, body extent -63,-63 63,62, height 319
Keystone5011 [mil] "Keystone Multipurpose loops"
  round 87 hole 63: 1(0,0)
  silkscreen extent -70,-70 70,70, body extent -63,-63 63,62, height 319
Keystone5012 [mil] "Keystone Multipurpose loops"
  round 87 hole 63: 1(0,0)
  silkscreen extent -70,-70 70,70, body extent -63,-63 63,62, height 319
Keystone5013 [mil] "Keystone Multipurpose loops"
  round 87 hole 63: 1(0,0)
  silkscreen extent -70,-70 70,70, body extent -63,-63 63,62, height 319
Keystone5014 [mil] "Keystone Multipurpose loops"
  round 87 hole 63: 1(0,0)
  silkscreen extent -70,-70 70,70, body extent -63,-63 63,62, height 319
Keystone5126 [mil] "Keystone Multipurpose loops"
  round 87 hole 63: 1(0,0)
  silkscreen extent -70,-70 70,70, body extent -63,-63 63,62, height 319
Keystone5127 [mil] "Keystone Multipurpose loops"
  round 87 hole 63: 1(0,0)
  silkscreen extent -70,-70 70,70, body extent -63,-63 63,62, height 319
Keystone5128 [mil] "Keystone Multipurpose loops"
  round 87 hole 63: 1(0,0)
  silkscreen extent -70,-70 70,70, body extent -63,-63 63,62, height 319
Keystone5129 [mil] "Keystone Multipurpose loops"
  round 87 hole 63: 1(0,0)
  silkscreen extent -70,-70 70,70, body extent -63,-63 63,62, height 319
LTSR6-NP [mm] "TH, 10-Leads, Body 10x22.2mm"
  rect 1.9x1.9 hole 1.4: 1(-0.73,5.85)
  round 1.9 hole 1.4: 2(1.81,5.85) 3(4.35,5.85) 4(4.35,-6.85) 5(1.81,-6.85) 6(-0.73,-6.85)
  round 1.4 hole 0.9: 7(-8.35,2.358) 8(-8.35,0.453) 9(-8.35,-1.452) 10(-8.35,-3.357)
  silkscreen extent -10.19,-5.65 12.01,5.2, body extent -10.19,-7.25 12.01,6.25, height 24
"NY PMS 440 0025 PH" [mm] "4-40 nylon screw and mounting hole"
  round 8 hole 3.2: 1(0,0)
  body extent -3.3,-3.3 3.3,3.3, height 2.69
PA0431LNL [mm] "TH, 2-Leads, Body 22.2x9.5mm, Pin Spacing 6.1mm"
  round 2.15 hole 1.65: 1(-3.05,0) 2(3.05,0)
  silkscreen extent -4.75,-11.1 4.75,11.1, body extent -4.75,-11.12 4.75,11.1, height 22.18
Pb-Free_Overlay_Medium [mil]
  silkscreen extent -95,-95 95,95
Phoenix_1714955 [mm] "Terminal Block, 2x1, 6.35mm, TH"
  rect 1.8x1.8 hole 1.3: 1(-3.175,0)
  round 1.8 hole 1.3: 2(3.175,0)
  silkscreen extent -6.7,-7.9 6.35,4.6, body extent -6.92,-7.9 6.35,4.6, height 21.5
